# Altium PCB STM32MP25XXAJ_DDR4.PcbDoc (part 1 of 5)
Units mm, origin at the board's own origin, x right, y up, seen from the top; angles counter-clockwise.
Board outline 172 x 137 mm, 4 copper layers (Top Layer, Signal Layer 1, Signal Layer 2, Bottom Layer), stack 1.614 mm thick; 226 components, 313 nets, 1113 pads, 850 vias.
Unrouted connection lines stored in the file: 13.
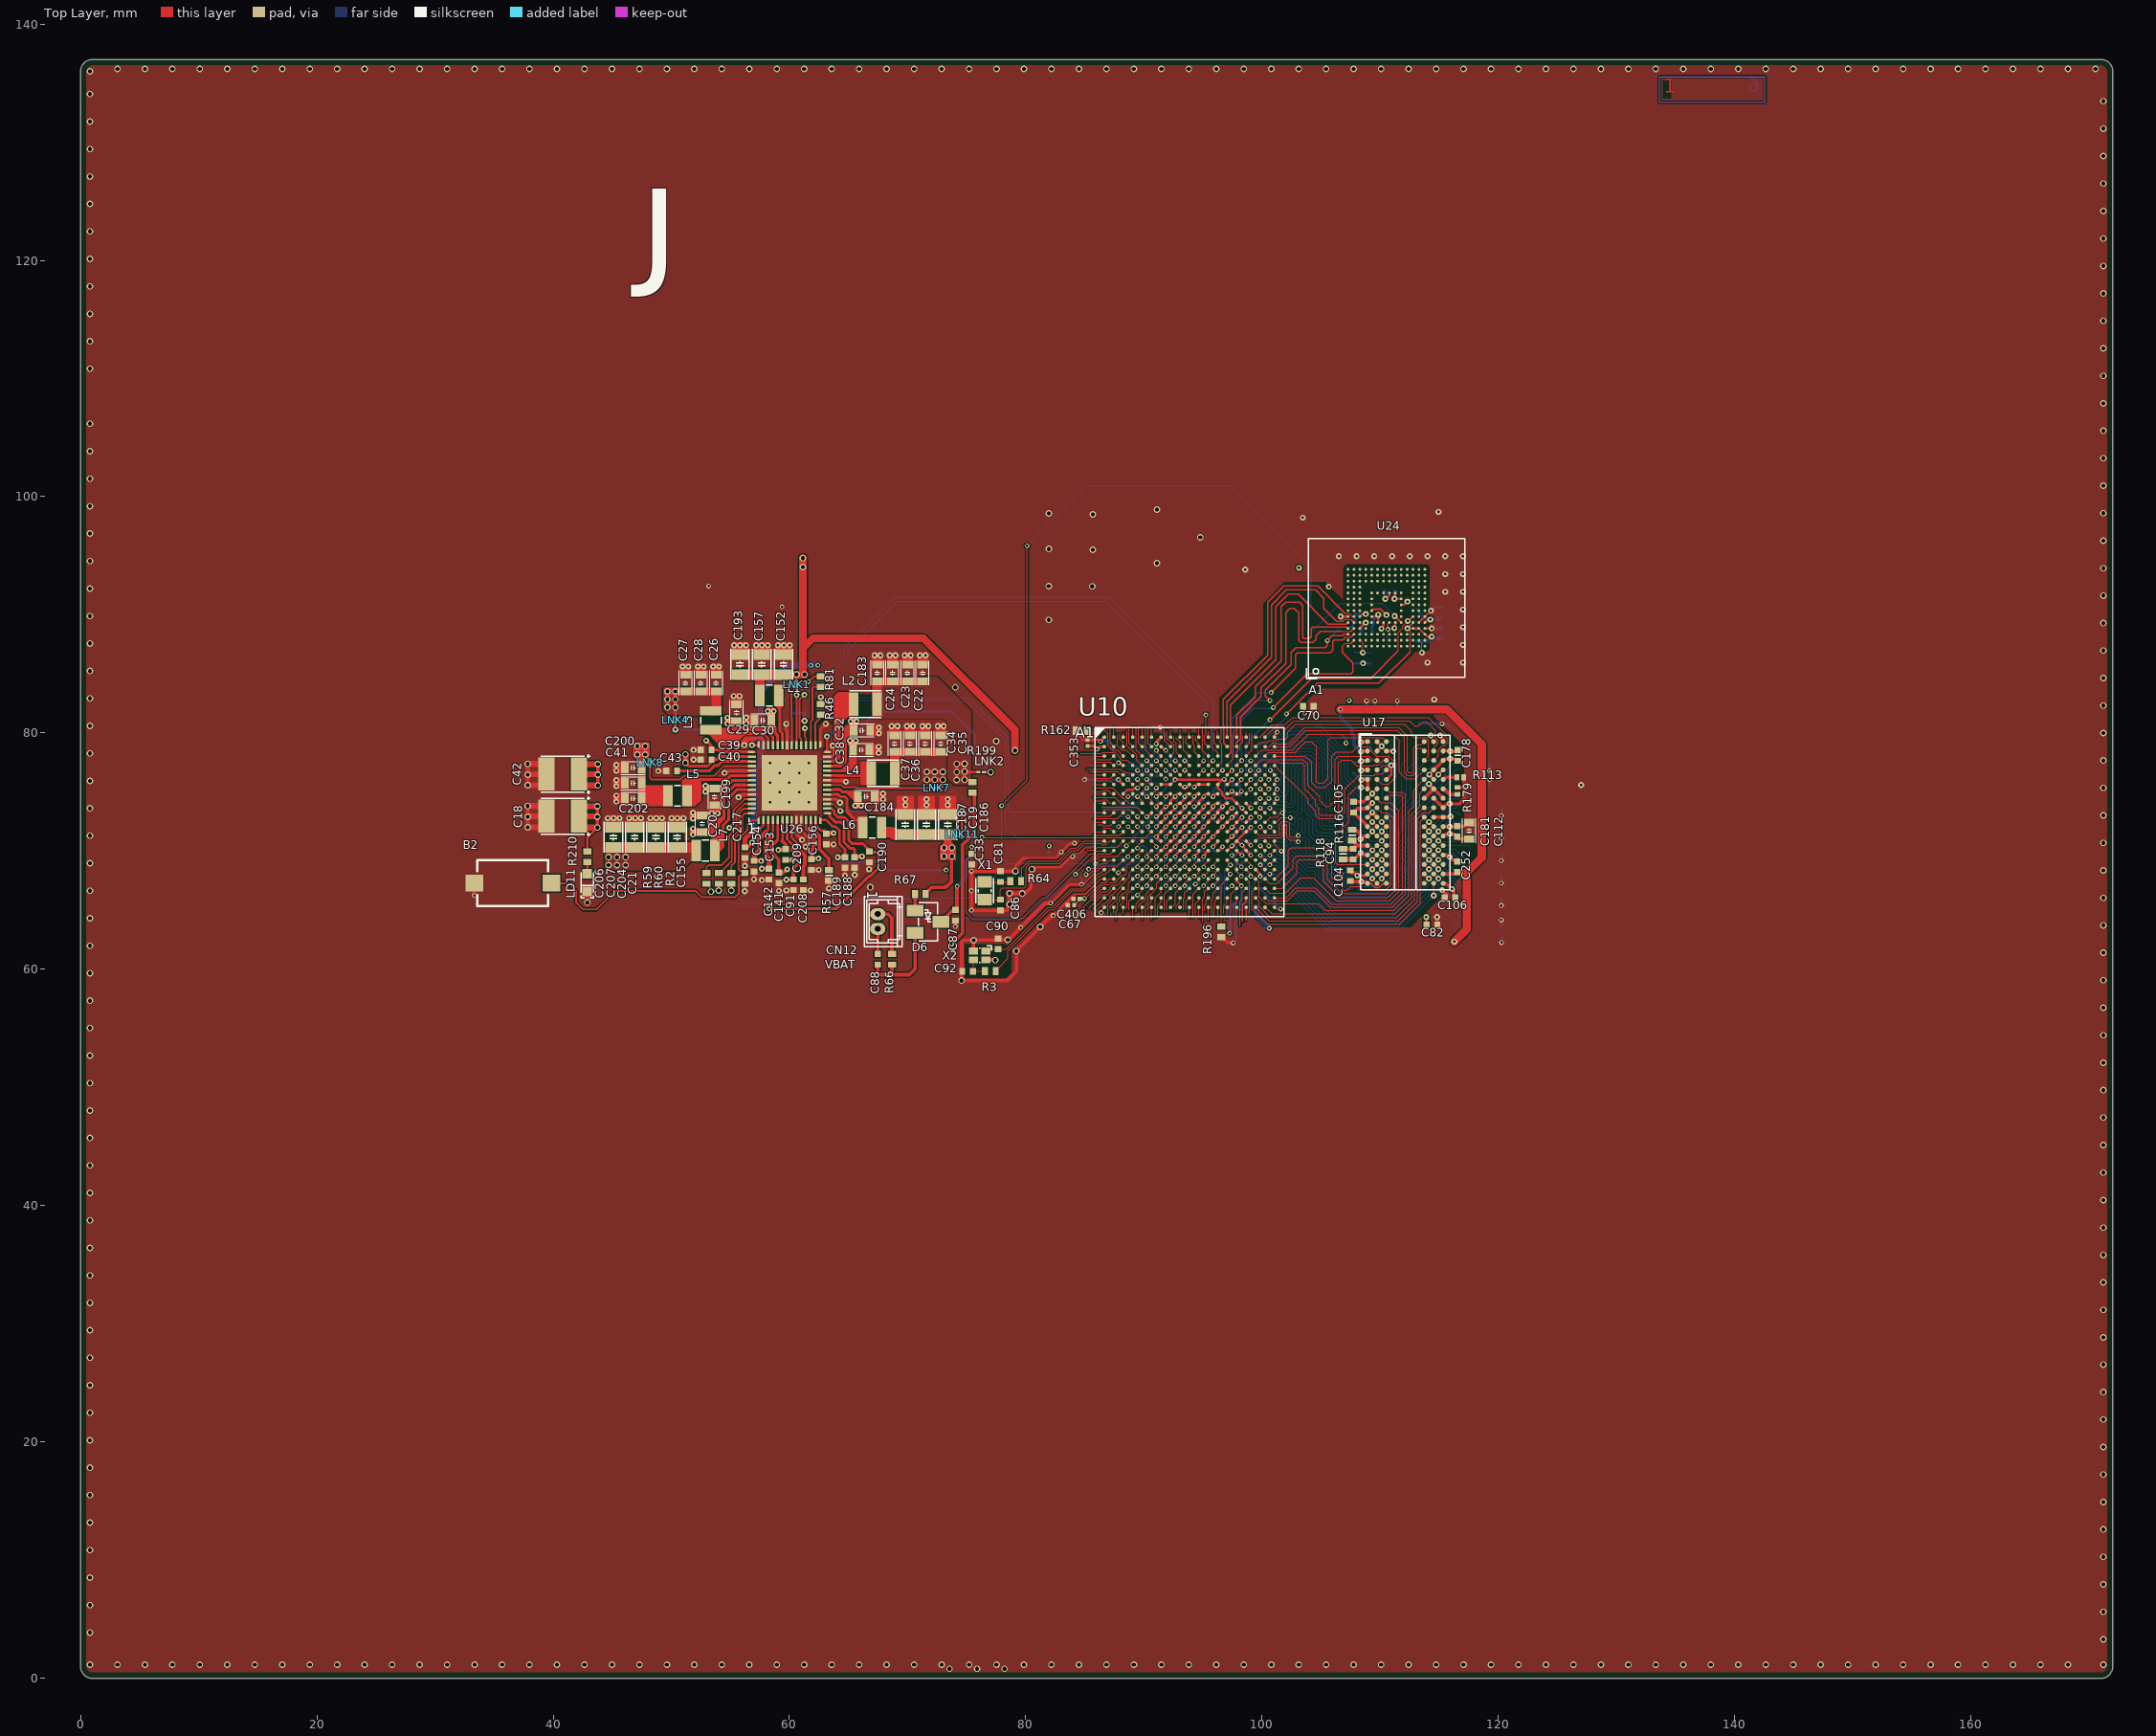
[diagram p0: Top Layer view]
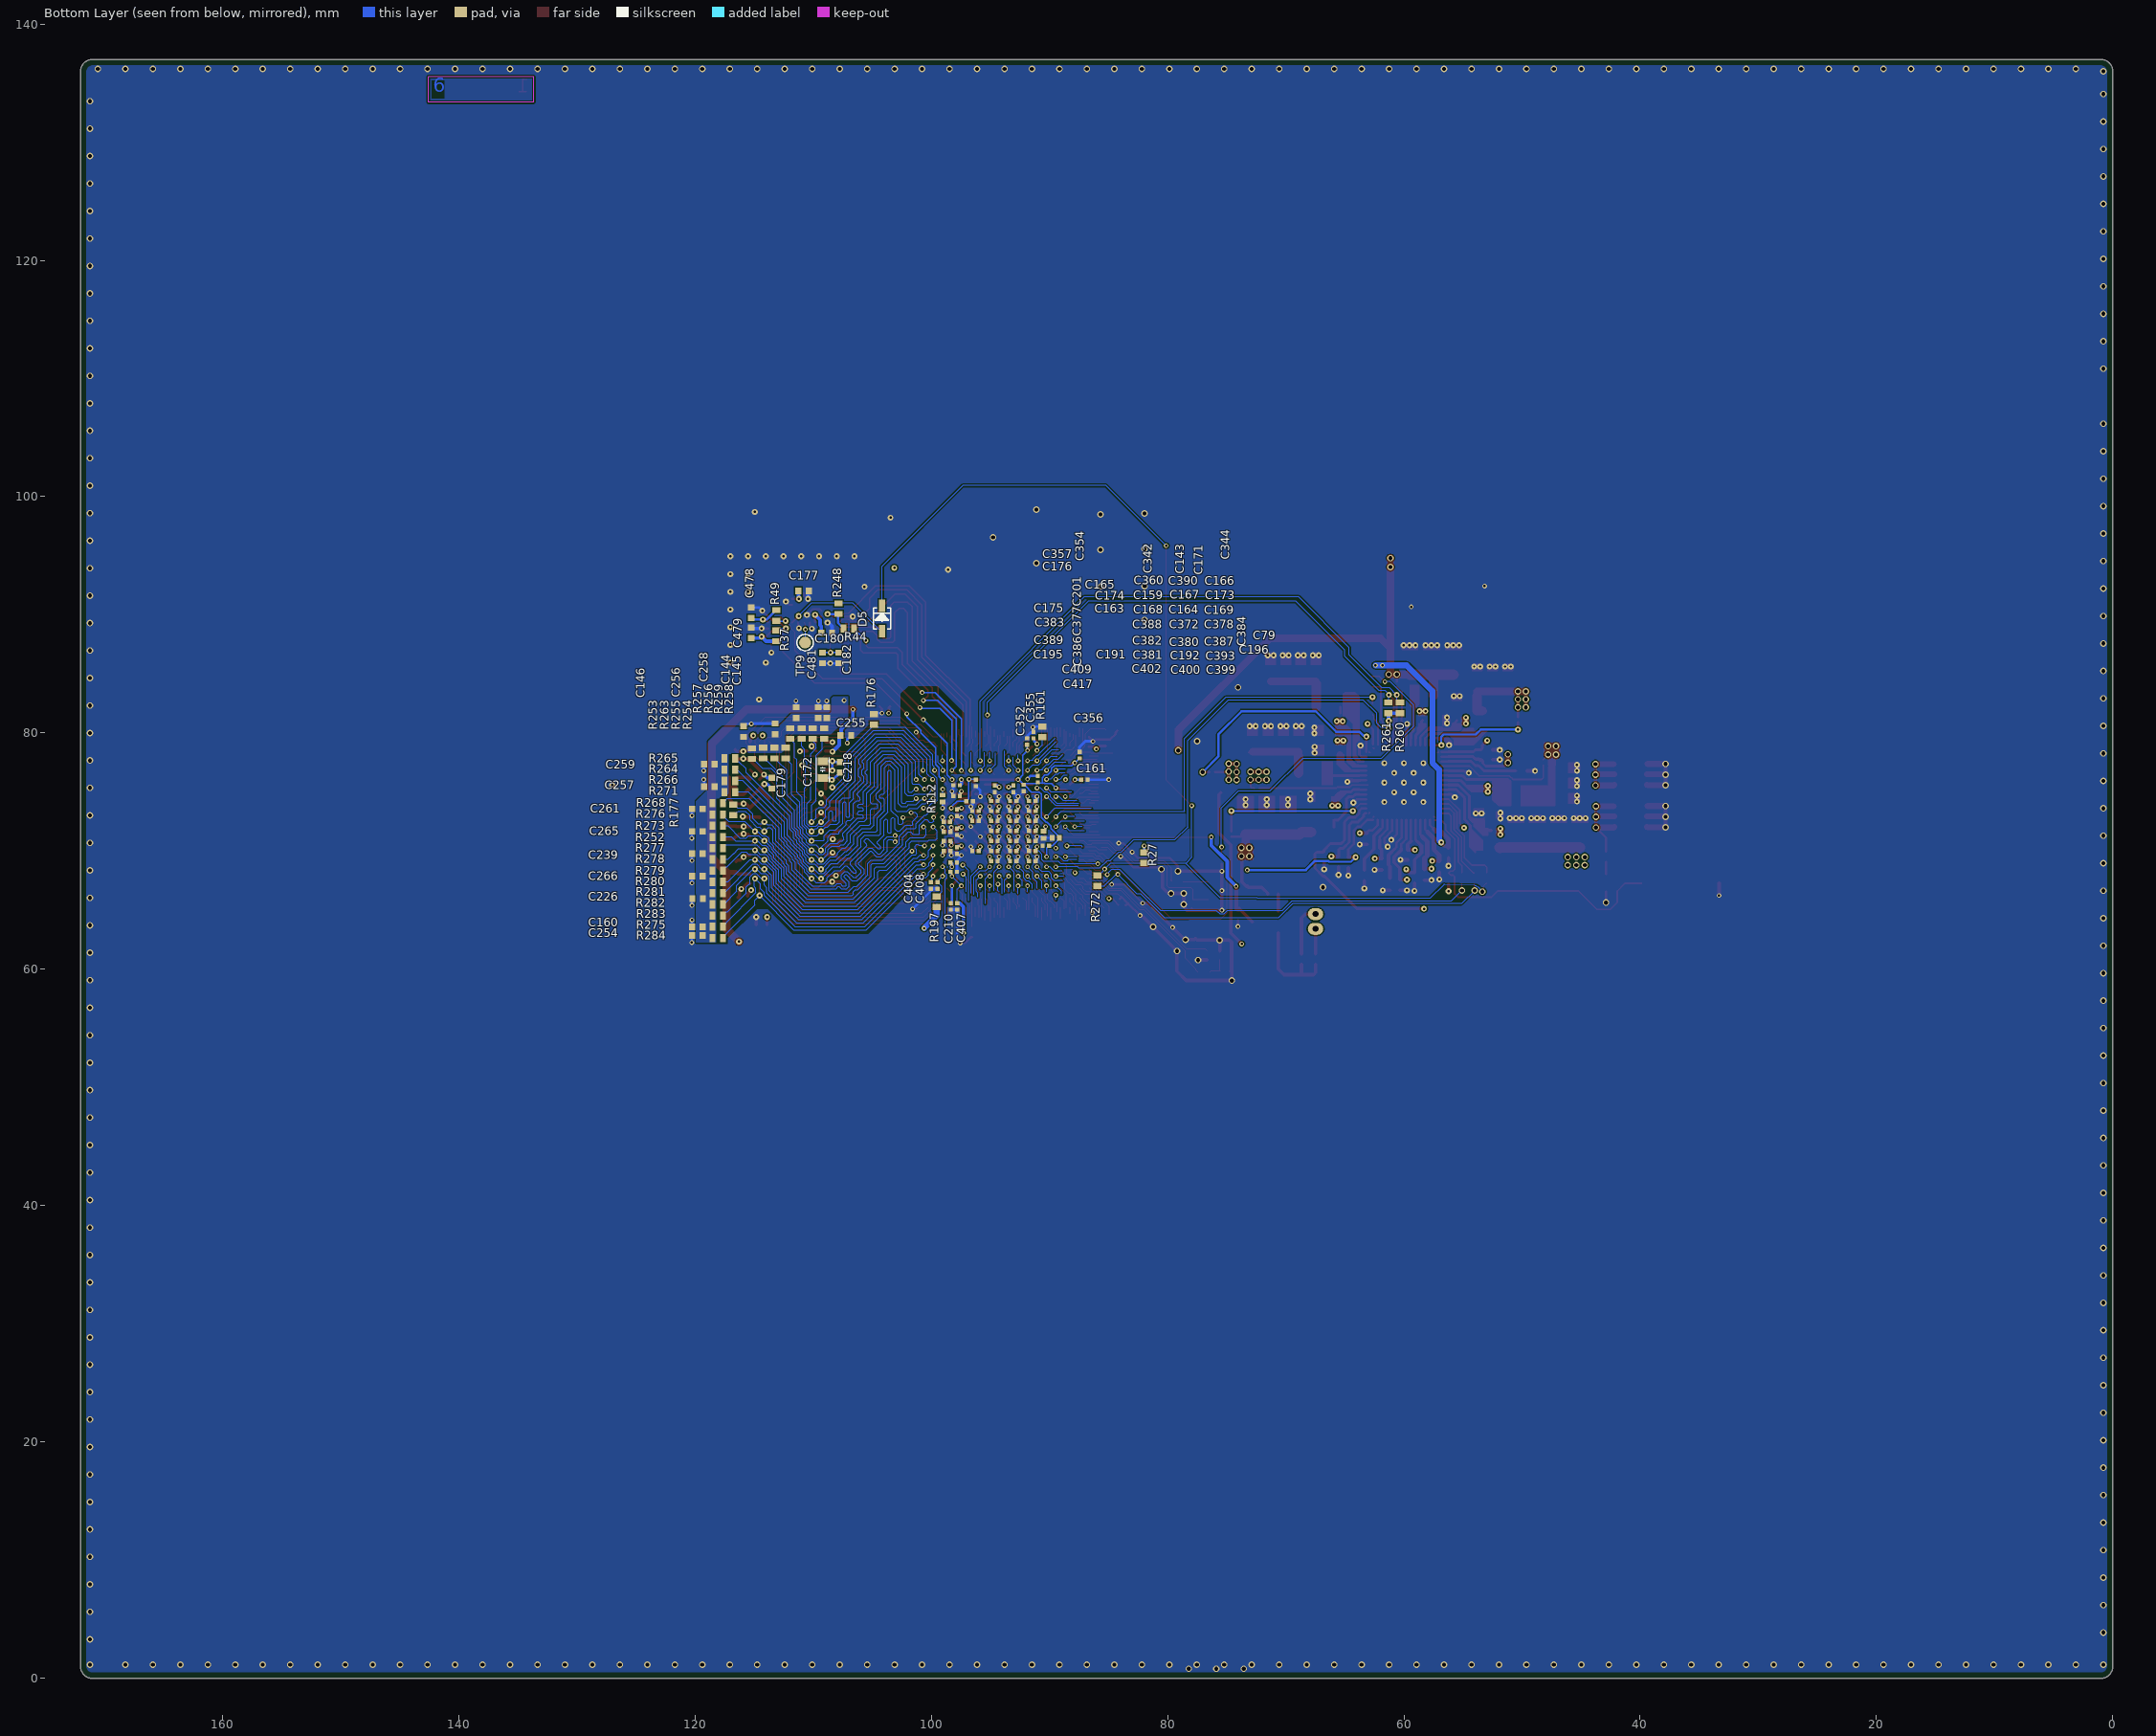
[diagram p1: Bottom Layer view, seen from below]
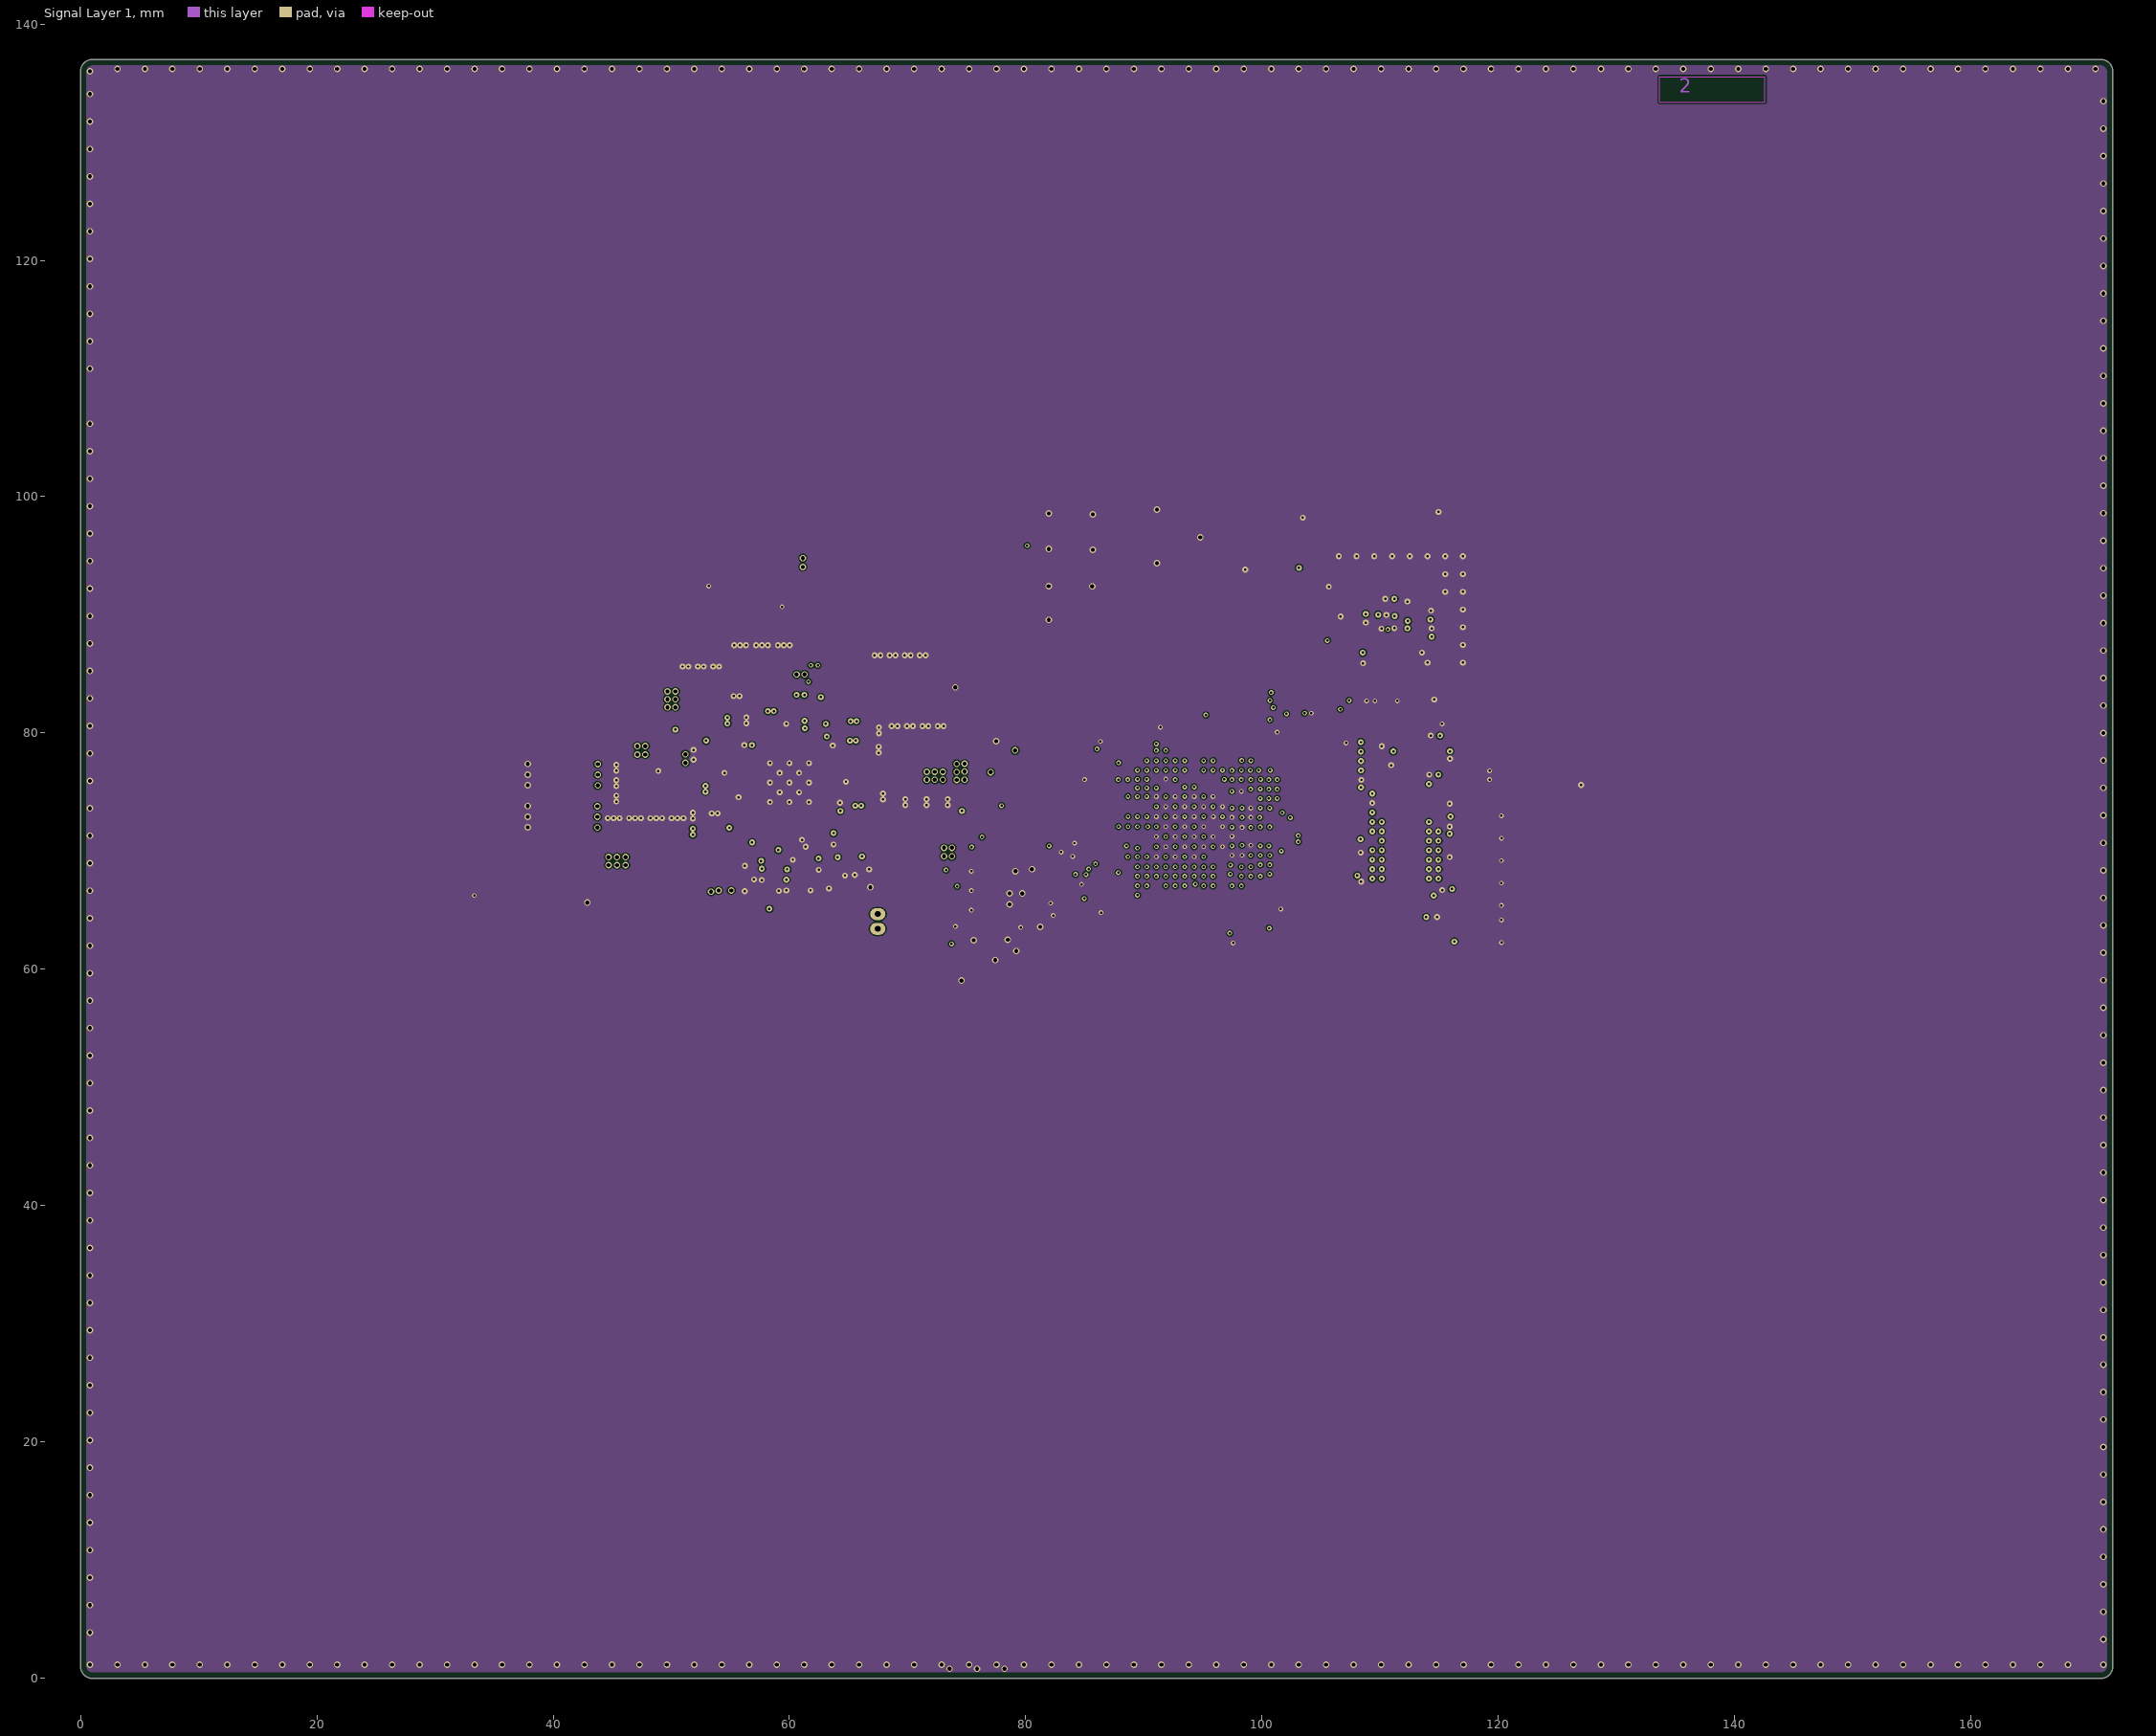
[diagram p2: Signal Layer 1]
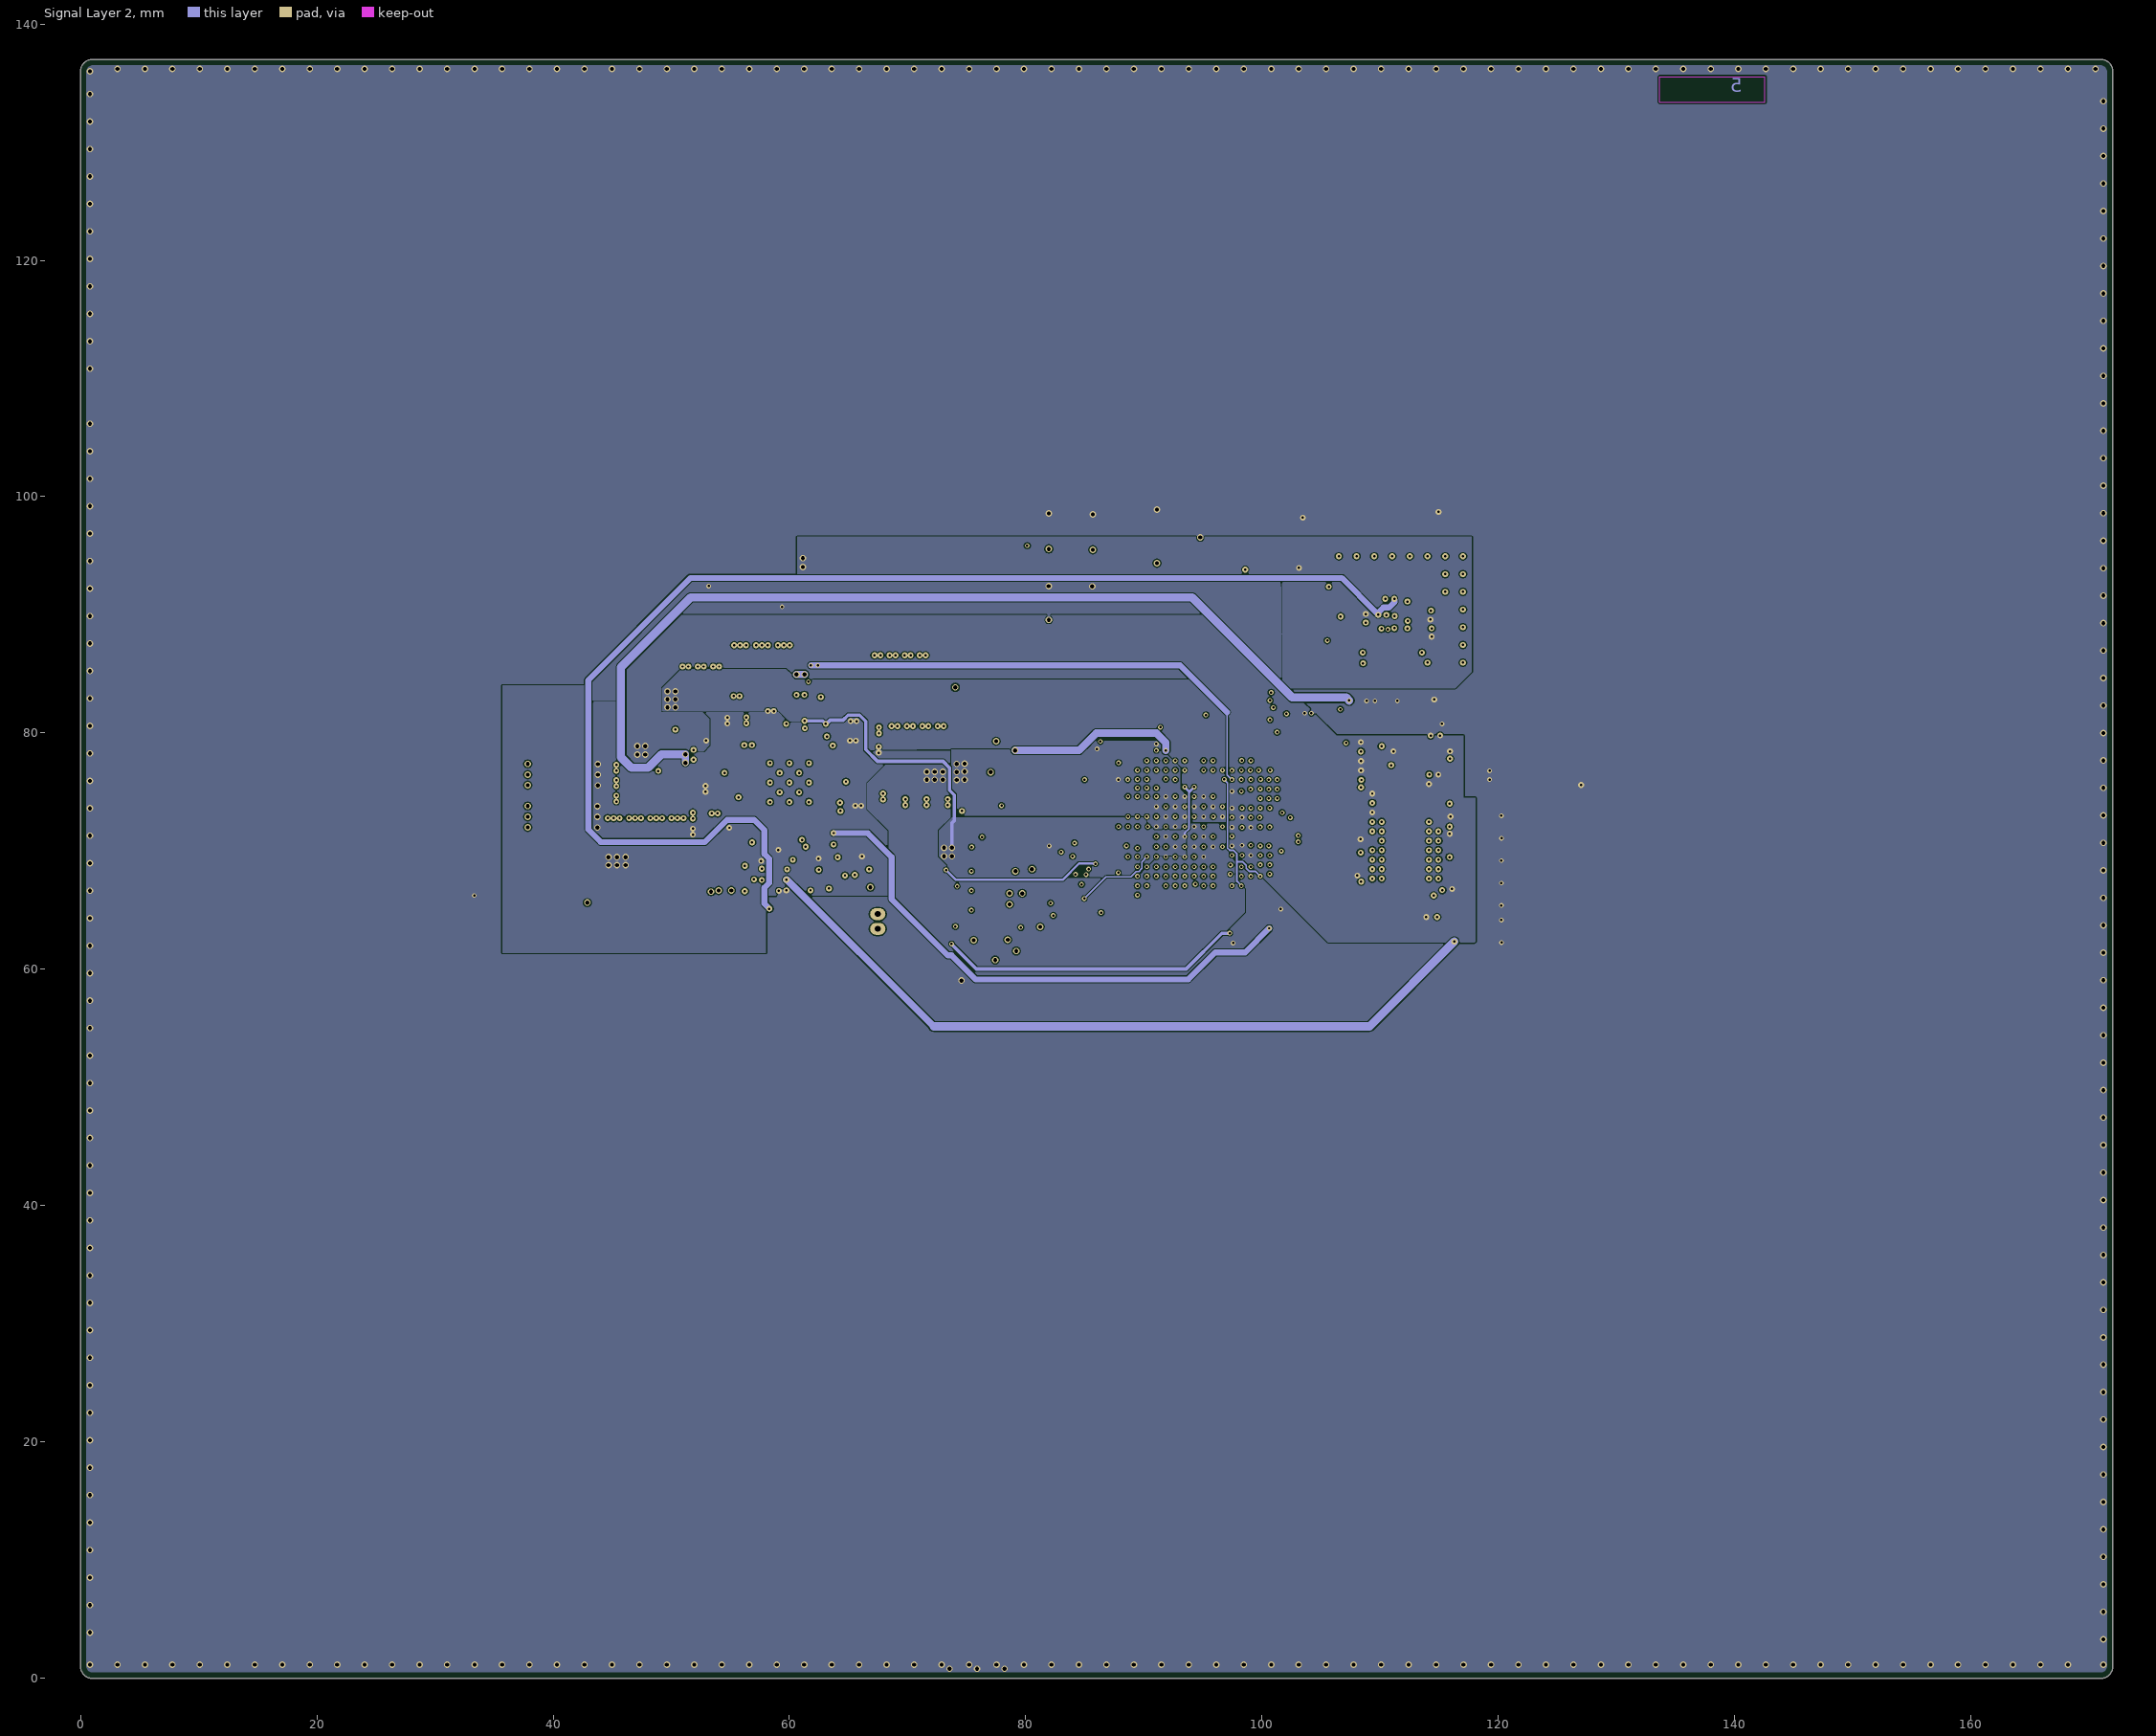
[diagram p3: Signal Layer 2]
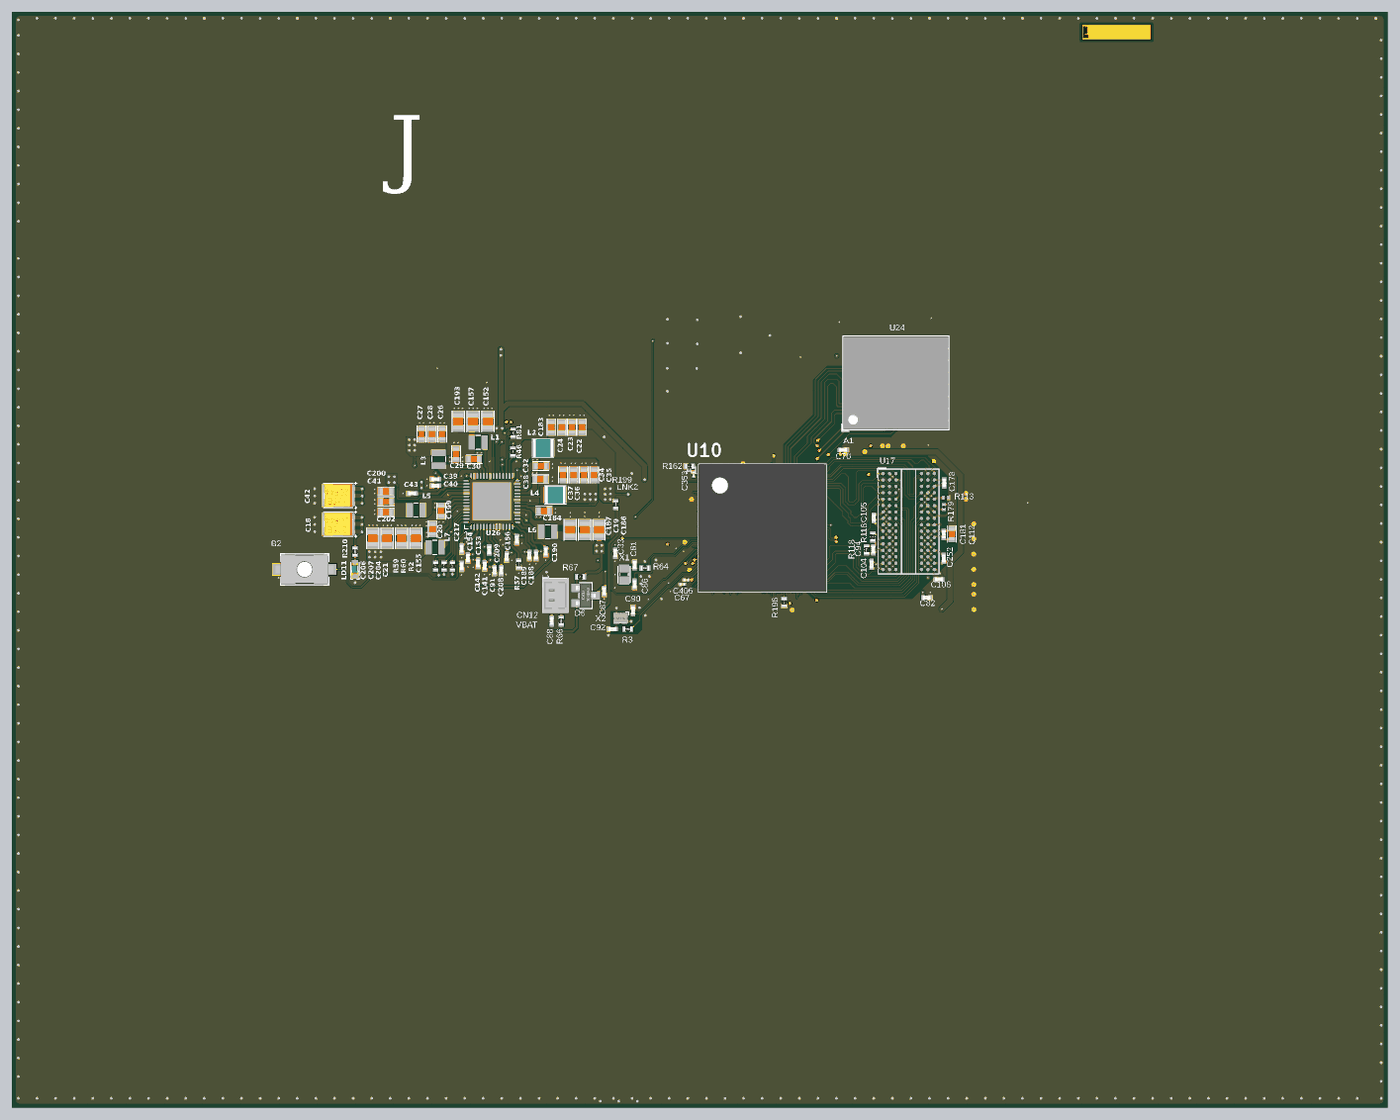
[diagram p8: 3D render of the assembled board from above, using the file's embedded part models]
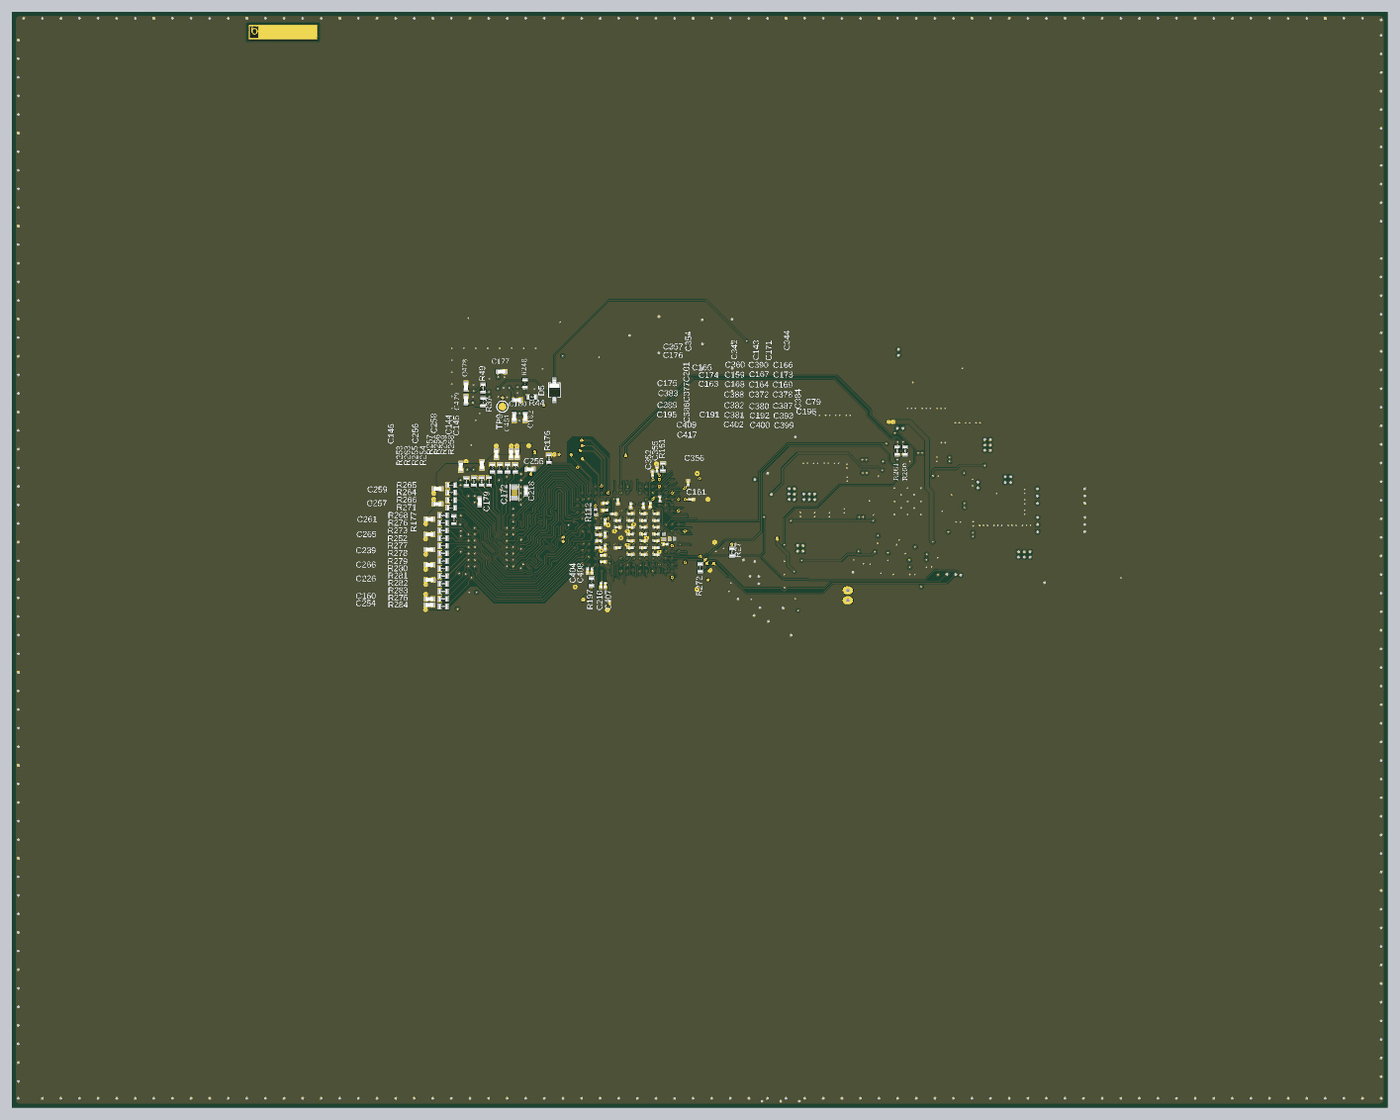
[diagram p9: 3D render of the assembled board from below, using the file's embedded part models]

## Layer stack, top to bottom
Top Solder: solder mask 0.025, Solder Resist, Dk 3.5
Top Layer: signal copper 0.037
Dielectric 1: prepreg 0.07, Dk 3.8
Signal Layer 1: signal copper 0.035
Dielectric 2: core 1.33, Dk 4.3
Signal Layer 2: signal copper 0.035
Dielectric 3: prepreg 0.07, Dk 3.8
Bottom Layer: signal copper 0.037
Bottom Solder: solder mask 0.025, Solder Resist, Dk 3.5

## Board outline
0,1 0,95 0,136 cw(c1,136) 1,137 171,137 cw(c171,136) 172,136 172,1 cw(c171,1) 171,0 1,0 cw(c1,1)

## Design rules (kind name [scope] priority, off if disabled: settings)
BoardOutlineClearance Silkscreen [OnLayer('Top Overlay') or OnLayer('Bottom Overlay')] p1: gap=0 ignorepadtopadclearanceinfootprint=FALSE
BoardOutlineClearance [All] p2: gap=0.5 ignorepadtopadclearanceinfootprint=FALSE
Clearance Clearance_Default [All] p1: gap=0.1 ignorepadtopadclearanceinfootprint=TRUE except(0: Arc-Hole Track-Hole SMDPad-Hole THPad-Hole Via-Hole Fill-Hole Poly-Hole Region-Hole Text-Hole; 0.09: Arc-Arc Arc-Track Arc-SMDPad Track-Track Track-SMDPad)
ComponentClearance [All] p1 off: gap=0.2 collisioncheckmode=3 verticalgap=0 showdistances=FALSE
DiffPairsRouting DiffPairsRouting_DDR_100R [InDifferentialPairClass('DPC_DDR_100R')] p1: maxlimit=0.16 minlimit=0.14 mostfreqgap=0.254 toplayer_mingap=0.16 toplayer_prefgap=0.16 toplayer_minwidth=0.09 toplayer_maxwidth=0.09 toplayer_prefwidth=0.09 bottomlayer_mingap=0.16 bottomlayer_prefgap=0.16 bottomlayer_minwidth=0.09 bottomlayer_maxwidth=0.09 bottomlayer_prefwidth=0.09 impedanceprofiledriven=TRUE impedanceprofileid={5106416E-43F8-41F8-8BCA-F68B3FB1C141} impedanceprofilevalue=100.000000 maxuncoupledlength=12.7
FanoutControl Fanout_BGA [IsBGA] p1: bgadir=Out bgaviamode=Closest fanoutstyle=Auto fanoutdirection=Alternating viagrid=0.025 // Fanout_BGA (Default Rule)
FanoutControl Fanout_LCC [IsLCC] p2: bgadir=Out bgaviamode=Closest fanoutstyle=Auto fanoutdirection=Alternating viagrid=0.025 // Fanout_LCC (Default Rule)
FanoutControl Fanout_SOIC [IsSOIC] p3: bgadir=Out bgaviamode=Closest fanoutstyle=Auto fanoutdirection=Alternating viagrid=0.025 // Fanout_SOIC (Default Rule)
FanoutControl Fanout_Small [(CompPinCount < 5)] p4: bgadir=Out bgaviamode=Closest fanoutstyle=Auto fanoutdirection=OutThenIn viagrid=0.025 // Fanout_Small (Default Rule)
FanoutControl Fanout_Default [All] p5: bgadir=Out bgaviamode=Closest fanoutstyle=Auto fanoutdirection=Alternating viagrid=0.025 // Fanout_Default (Default Rule)
HoleSize [All] p1: absolutevalues=TRUE maxlimit=10 minlimit=0.025 maxpercent=80.000 minpercent=20.000
HoleToHoleClearance [All] p1: gap=0.25 allowstackedmicrovias=TRUE
MinimumSolderMaskSliver [All] p1: minsoldermaskwidth=0.07
PlaneConnect [All] p1: planeconnectstyle=Direct reliefexpansion=0.508 reliefentries=4 reliefconductorwidth=0.21 reliefairgap=0.21
PolygonConnect PolygonConnect_Default [All] p1: connectstyle=Direct reliefconductorwidth=0.25 reliefentries=4 polygonreliefangle="90 Angle" airgapwidth=0.25
RoomDefinition U_PMIC [InComponentClass('U_PMIC')] p1: confinementstyle=ConfineIn formatcopy=TRUE lockcomponents=FALSE outline -226.399,-195.173 -175.599,-195.173 -175.599,-169.773 -226.399,-169.773
RoomDefinition U_eMMC [InComponentClass('U_eMMC')] p2: confinementstyle=ConfineIn formatcopy=TRUE lockcomponents=FALSE outline -226.399,-195.173 -175.599,-195.173 -175.599,-169.773 -226.399,-169.773
RoomDefinition U_DDR4_16bits [InComponentClass('U_DDR4_16bits')] p3: confinementstyle=ConfineIn formatcopy=TRUE lockcomponents=FALSE outline 173.143,1.397 598.552,1.397 598.552,17.691 173.143,17.691
RoutingVias RoutingVias_Default [All] p1: holewidth=0.15 width=0.4 viastyle="Through Hole" minholewidth=0.15 minwidth=0.4 maxholewidth=0.35 maxwidth=0.6 viatemplateguid#1={A479BBDC-94B7-4D18-B59D-B7A18B767B5F} viatemplateguid#2={564DD7E2-F718-4BCE-8A99-5417C9FECCB6} viatemplateguid#3={BA919398-BDEC-4FED-AED0-6BF9ED2A8C2F} viatemplateguid#4={BB8F4C89-420F-4EBC-9772-FD82009DE81A} viatemplateguid#5={3FF096CA-B7A5-4E0B-A50A-8B2CD18CCC19} viatemplatename#1=v55h35m40mx40 viatemplatename#2=v40h20m0mx0 viatemplatename#3=v50h25m30mx30 viatemplatename#4=v40h20m25mx25 viatemplatename#5=v50h25m0mx0
ShortCircuit ShortCircuit_Link200 [InPadClass('PC_LINK200')] p1: allowed=TRUE
SilkToSilkClearance [All] p1: silktosilkclearance=0.2
SilkToSolderMaskClearance [IsPad] p1: minsilkscreentomaskgap=0.015 clearancetoexposedcopper=TRUE
SolderMaskExpansion [All] p1: expansion=0.1 istentingtop=FALSE
ViasUnderSMD [InPadClass('PC_VIAS-IN-PAD_OK')] p1: allowed=TRUE
Width Width_Default [InNetClass('All Nets')] p1: maxlimit=10 minlimit=0.09 preferedwidth=0.1
16 further rules are at their usual default settings.

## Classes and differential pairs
net class eMMC.SDMMC2_D[0..7]: eMMC.SDMMC2_D0 eMMC.SDMMC2_D1 eMMC.SDMMC2_D2 eMMC.SDMMC2_D3 eMMC.SDMMC2_D4 eMMC.SDMMC2_D5 eMMC.SDMMC2_D6 eMMC.SDMMC2_D7
component class "U_STM32MP25XXAJ Power": C67 C79 C87 C88 C143 C159 C161 C163 C164 C165 C166 C167 C168 C169 C171 C173 C174 C175 C176 C191 C192 C195 C196 C201 C210 C342 C344 C352 C353 C354 C355 C356 C357 C360 C372 C377 C378 C380 C381 C382 C383 C384 C386 C387 C388 C389 C390 C393 C399 C400 C402 C404 C406 C407 C408 C409 C417 CN12 D6 R66 R67 R197 R199
component class "U_STM32MP25XXAJ I_Os": C33 C81 C86 C90 C92 R3 R27 R64 R161 R162 R196 R260 R261 R272 U10 X1 X2
component class U_PMIC: B2 C18 C19 C20 C21 C22 C23 C24 C26 C27 C28 C29 C30 C32 C34 C35 C36 C37 C38 C39 C40 C41 C42 C43 C91 C141 C142 C152 C153 C154 C155 C156 C157 C183 C184 C186 C187 C188 C189 C190 C193 C199 C200 C202 C204 C206 C207 C208 C209 C217 L1 L2 L3 L4 L5 L6 L7 LD11 LNK1 LNK2 LNK4 LNK7 LNK8 LNK11 R2 R46 R57 R59 R60 R81 R210 U26
component class U_eMMC: C177 C180 C182 C478 C479 C481 D5 R37 R44 R49 R248 TP9 U24
component class U_DDR4_16bits: C70 C82 C94 C104 C105 C106 C112 C144 C145 C146 C160 C172 C178 C179 C181 C218 C226 C239 C252 C254 C255 C256 C257 C258 C259 C261 C265 C266 R112 R113 R116 R118 R176 R177 R179 R252 R253 R254 R255 R256 R257 R258 R259 R263 R264 R265 R266 R268 R271 R273 R275 R276 R277 R278 R279 R280 R281 R282 R283 R284 U17
differential pair DDR_DQS1: +DDR_DQS1_P -DDR_DQS1_N
differential pair DDR_DQS0: +DDR_DQS0_P -DDR_DQS0_N
differential pair DDR_CLK: +DDR_CLK_P -DDR_CLK_N

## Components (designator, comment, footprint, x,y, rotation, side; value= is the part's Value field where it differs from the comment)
B2 "SW_PUSH_SMD_2P" SWI_WE_434121025816 36.59,67.295 r0 top value=434121025816
C18 "Cap_POL_TANA" CPOL_TCJ-B_1210_H210 40.812,72.961 r180 top value=100uF
C19 "Capacitor" C0805 71.6,72.25 r270 top value=22uF
C20 "Capacitor" C0603 52.6,72.325 r270 top value=10uF
C21 "Capacitor" C0805 50.5,71.173 r270 top value=22uF
C22 "Capacitor" C0603 71.275,85.075 r270 top value=22uF
C23 "Capacitor" C0603 70,85.075 r270 top value=22uF
C24 "Capacitor" C0603 68.725,85.075 r270 top value=22uF
C26 "Capacitor" C0603 53.8,84.225 r270 top value=22uF
C27 "Capacitor" C0603 51.2,84.225 r270 top value=22uF
C28 "Capacitor" C0603 52.5,84.225 r270 top value=22uF
C29 "Capacitor" C0603 55.525,81.725 r270 top value=10uF
C30 "Capacitor" C0603 57.75,81.075 r0 top value=10uF
C32 "Capacitor" C0603 66.125,80.225 r180 top value=10uF
C33 "Capacitor" C0402 75.425,69.325 r90 top value=10nF
C34 "Capacitor" C0603 71.5,79.1 r270 top value=22uF
C35 "Capacitor" C0603 72.8,79.1 r270 top value=22uF
C36 "Capacitor" C0603 70.2,79.1 r270 top value=22uF
C37 "Capacitor" C0603 68.9,79.1 r270 top value=22uF
C38 "Capacitor" C0603 66.075,78.575 r180 top value=10uF
C39 "Capacitor" C0402 52.945,78.575 r0 top value=10uF
C40 "Capacitor" C0402 52.945,77.75 r0 top value=10uF
C41 "Capacitor" C0603 46.775,75.75 r0 top value=22uF
C42 "Cap_POL_TANA" CPOL_TCJ-B_1210_H210 40.812,76.523 r180 top value=100uF
C43 "Capacitor" C0402 50.035,76.8 r0 top value=1uF
C67 "Capacitor" C0201_MURATA_GRM033_H0P3 83.825,65.425 r0 top value=1uF
C70 "Capacitor" C0402 103.925,82.25 r180 top value=100nF
C79 "Capacitor" C0201_H0P5 89.45,71.125 r180 bottom value=2.2uF
C81 "Capacitor" C0402 77.85,67.85 r90 top value=6.8pF
C82 "Capacitor" C0402 114.375,63.775 r180 top value=100nF
C86 "Capacitor" C0402 77.85,65.45 r270 top value=6.8pF
C87 "" C0402 74.05,64.575 r90 top value=100nF
C88 "Capacitor" C0402 67.475,60.85 r270 top value=2.2uF
C90 "Capacitor" C0402 77.65,62.15 r270 top value=6.8pF
C91 "Capacitor" C0402 60.345,67.16 r270 top value=4.7uF
C92 "Capacitor" C0402 75.075,59.825 r180 top value=6.8pF
C94 "Capacitor" C0402 107.7,69.75 r90 top value=100nF
C104 "Capacitor" C0402 107.475,67.925 r90 top value=100nF
C105 "Capacitor" C0402 107.75,73.725 r90 top value=100nF
C106 "Capacitor" C0402 115.9,66.05 r0 top value=100nF
C112 "Capacitor" C0603 117.525,71.725 r270 top value=10uF
C141 "Capacitor" C0402 59.1,67.75 r270 top value=4.7uF
C142 "Capacitor" C0402 58.275,68.06 r270 top value=4.7uF
C143 "Capacitor" C0201_MURATA_GRM033_H0P3 93.05,75.275 r90 bottom value=100nF
C144 "Capacitor" C0402 109.575,81.725 r270 bottom value=100nF
C145 "Capacitor" C0402 108.825,81.725 r270 bottom value=10uF
C146 "Capacitor" C0402 115.875,80.125 r270 bottom value=100nF
C152 "Capacitor" C0805 59.5,85.8 r270 top value=22uF
C153 "Capacitor" C0402 59.675,69.72 r90 top value=1uF
C154 "Capacitor" C0402 57,68.725 r90 top value=1uF
C155 "Capacitor" C0402 56.227,67.695 r90 top value=10nF
C156 "Capacitor" C0402 63.125,71.02 r90 top value=4.7uF
C157 "Capacitor" C0805 57.65,85.8 r270 top value=22uF
C159 "Capacitor" C0201_MURATA_GRM033_H0P3 94.65,73.4 r180 bottom value=1uF
C160 "Capacitor" C0402 119.8,63.6 r180 bottom value=100nF
C161 "Capacitor" C0201_MURATA_GRM033_H0P3 87.05,76.05 r0 bottom value=100nF
C163 "Capacitor" C0201_MURATA_GRM033_H0P3 96.25,72.55 r0 bottom value=1uF
C164 "Capacitor" C0201_MURATA_GRM033_H0P3 93.05,72.55 r180 bottom value=1uF
C165 "Capacitor" C0201_MURATA_GRM033_H0P3 96.75,74.225 r0 bottom value=100nF
C166 "Capacitor" C0201_MURATA_GRM033_H0P3 91.45,74.25 r0 bottom value=1uF
C167 "Capacitor" C0201_MURATA_GRM033_H0P3 93.05,73.4 r180 bottom value=1uF
C168 "Capacitor" C0201_MURATA_GRM033_H0P3 94.65,72.55 r0 bottom value=1uF
C169 "Capacitor" C0201_MURATA_GRM033_H0P3 91.45,72.55 r0 bottom value=1uF
C171 "Capacitor" C0201_MURATA_GRM033_H0P3 92.175,75.35 r90 bottom value=100nF
C172 "Capacitor" C0603 109.175,76.9 r90 bottom value=10uF
C173 "Capacitor" C0201_MURATA_GRM033_H0P3 91.45,73.4 r0 bottom value=1uF
C174 "Capacitor" C0201_MURATA_GRM033_H0P3 96.25,73.4 r0 bottom value=1uF
C175 "Capacitor" C0201_MURATA_GRM033_H0P3 98.675,72.475 r180 bottom value=1uF
C176 "Capacitor" C0201_MURATA_GRM033_H0P3 97.85,74.675 r180 bottom value=1uF
C177 "Capacitor" C0402 110.8,92.025 r0 bottom value=100nF
C178 "Capacitor" C0402 116.575,78.1 r90 top value=100nF
C179 "Capacitor" C0402 113.5,75.75 r270 bottom value=100nF
C180 "Capacitor" C0402 108.85,88.475 r0 bottom value=2.2uF
C181 "Capacitor" C0402 116.515,71.67 r270 top value=100nF
C182 "Capacitor" C0402 107.825,86.35 r90 bottom value=100nF
C183 "Capacitor" C0603 67.45,85.075 r270 top value=22uF
C184 "Capacitor" C0603 66.497,74.625 r180 top value=10uF
C186 "Capacitor" C0805 73.4,72.25 r270 top value=22uF
C187 "Capacitor" C0805 69.8,72.25 r270 top value=22uF
C188 "Capacitor" C0402 65.525,69.04 r90 top value=1uF
C189 "Capacitor" C0402 64.7,69.04 r90 top value=4.7uF
C190 "Capacitor" C0402 66.75,69.515 r270 top value=4.7uF
C191 "Capacitor" C0201_MURATA_GRM033_H0P3 96.25,70 r0 bottom value=1uF
C192 "Capacitor" C0201_MURATA_GRM033_H0P3 93.05,70 r180 bottom value=1uF
C193 "Capacitor" C0805 55.8,85.8 r270 top value=22uF
C195 "Capacitor" C0201_MURATA_GRM033_H0P3 98.65,70.025 r0 bottom value=1uF
C196 "Capacitor" C0201_MURATA_GRM033_H0P3 90.3,70.45 r180 bottom value=100nF
C199 "Capacitor" C0603 53.675,74.6 r90 top value=10uF
C200 "Capacitor" C0603 46.775,77.05 r0 top value=22uF
C201 "Capacitor" C0201_MURATA_GRM033_H0P3 97.825,73.25 r90 bottom value=1uF
C202 "Capacitor" C0603 46.775,74.45 r0 top value=22uF
C204 "Capacitor" C0805 48.7,71.173 r270 top value=22uF
C206 "Capacitor" C0805 45.1,71.173 r270 top value=22uF
C207 "Capacitor" C0805 46.9,71.173 r270 top value=22uF
C208 "Capacitor" C0402 61.17,67.16 r270 top value=4.7uF
C209 "Capacitor" C0402 61.85,68.87 r90 top value=4.7uF
C210 "Capacitor" C0201_MURATA_GRM033_H0P3 98.35,65.325 r90 bottom value=100nF
C217 "Capacitor" C0402 56.225,69.87 r270 top value=4.7uF
C218 "Capacitor" C0402 107.725,77.1 r90 bottom value=100nF
C226 "Capacitor" C0402 119.775,65.975 r180 bottom value=100nF
C239 "Capacitor" C0402 119.8,69.775 r180 bottom value=100nF
C252 "Capacitor" C0402 116.515,68.67 r270 top value=100nF
C254 "Capacitor" C0402 119.8,62.85 r180 bottom value=10uF
C255 "Capacitor" C0402 107.225,79.8 r0 bottom value=100nF
C256 "Capacitor" C0402 113.225,80.35 r270 bottom value=100nF
C257 "Capacitor" C0402 118.775,75.475 r180 bottom value=100nF
C258 "Capacitor" C0402 111.425,81.725 r270 bottom value=100nF
C259 "Capacitor" C0402 118.775,77.375 r180 bottom value=100nF
C261 "Capacitor" C0402 119.8,73.575 r180 bottom value=100nF
C265 "Capacitor" C0402 119.8,71.675 r180 bottom value=100nF
C266 "Capacitor" C0402 119.8,67.875 r180 bottom value=100nF
C342 "Capacitor" C0201_MURATA_GRM033_H0P3 94.625,75.275 r90 bottom value=100nF
C344 "Capacitor" C0201_MURATA_GRM033_H0P3 90.975,76.1 r270 bottom value=100nF
C352 "Capacitor" C0201_MURATA_GRM033_H0P3 91.9,79.275 r270 bottom value=100nF
C353 "Capacitor" C0201_MURATA_GRM033_H0P3 85.225,79.175 r270 top value=100nF
C354 "Capacitor" C0201_MURATA_GRM033_H0P3 96.224,75.776 r90 bottom value=100nF
C355 "Capacitor" C0201_MURATA_GRM033_H0P3 91.35,79.825 r270 bottom value=100nF
C356 "Capacitor" C0201_MURATA_GRM033_H0P3 87.45,78.125 r270 bottom value=100nF
C357 "Capacitor" C0201_MURATA_GRM033_H0P3 97.85,75.575 r180 bottom value=100nF
C360 "Capacitor" C0201_MURATA_GRM033_H0P3 94.65,74.25 r180 bottom value=1uF
C372 "Capacitor" C0201_MURATA_GRM033_H0P3 93.05,71.7 r180 bottom value=1uF
C377 "Capacitor" C0201_MURATA_GRM033_H0P3 97.825,71.65 r90 bottom value=1uF
C378 "Capacitor" C0201_MURATA_GRM033_H0P3 91.45,71.7 r180 bottom value=1uF
C380 "Capacitor" C0201_MURATA_GRM033_H0P3 93.05,70.85 r0 bottom value=1uF
C381 "Capacitor" C0201_MURATA_GRM033_H0P3 94.65,70 r180 bottom value=1uF
C382 "Capacitor" C0201_MURATA_GRM033_H0P3 94.65,70.85 r0 bottom value=1uF
C383 "Capacitor" C0201_MURATA_GRM033_H0P3 98.65,71.625 r0 bottom value=1uF
C384 "Capacitor" C0201_H0P5 90.5,71.375 r90 bottom value=4.7uF
C386 "Capacitor" C0201_MURATA_GRM033_H0P3 97.825,70.05 r90 bottom value=1uF
C387 "Capacitor" C0201_MURATA_GRM033_H0P3 91.45,70.85 r180 bottom value=1uF
C388 "Capacitor" C0201_MURATA_GRM033_H0P3 94.65,71.7 r180 bottom value=1uF
C389 "Capacitor" C0201_MURATA_GRM033_H0P3 98.65,70.875 r0 bottom value=1uF
C390 "Capacitor" C0201_MURATA_GRM033_H0P3 93.05,74.25 r0 bottom value=1uF
C393 "Capacitor" C0201_MURATA_GRM033_H0P3 91.45,70 r180 bottom value=100nF
C399 "Capacitor" C0201_MURATA_GRM033_H0P3 91.45,69.15 r180 bottom value=1uF
C400 "Capacitor" C0201_MURATA_GRM033_H0P3 93.05,69.15 r0 bottom value=1uF
C402 "Capacitor" C0201_MURATA_GRM033_H0P3 94.65,69.15 r0 bottom value=1uF
C404 "Capacitor" C0201_MURATA_GRM033_H0P3 100.025,67.1 r90 bottom value=100nF
C406 "Capacitor" C0201_MURATA_GRM033_H0P3 84.3,65.975 r0 top value=100nF
C407 "Capacitor" C0201_MURATA_GRM033_H0P3 97.8,65.325 r90 bottom value=100nF
C408 "Capacitor" C0201_MURATA_GRM033_H0P3 99.475,67.101 r90 bottom value=100nF
C409 "Capacitor" C0201_MURATA_GRM033_H0P3 98.1,69.05 r0 bottom value=100nF
C417 "Capacitor" C0201_MURATA_GRM033_H0P3 98.1,68.25 r0 bottom value=100nF
C478 "Capacitor" C0402 115.225,90.175 r270 bottom value=2.2uF
C479 "Capacitor" C0402 115.225,88.475 r270 bottom value=100nF
C481 "Capacitor" C0402 109.2,86.35 r90 bottom value=2.2uF
CN12 "" CON_MOLEX_53047-0210 67.475,64.05 r270 top value="Header 2x1"
D5 "BAT60JFILM" DIO_SOD323 104.175,89.7 r90 bottom
D6 "DIODE_3P_DUAL_COMMON_CATHODE" DIO_SOT23 71.725,64.025 r270 top value=BAT54CFILM
L1 "Inductor" IND_2016_MURATA_LQM2MPN2R2NG0 58.295,83.175 r180 top value=2.2uH
L2 "Inductor" IND_2520_TOKO_DFE252012P 66.415,82.45 r0 top value=0.68µH
L3 "Inductor" IND_2016_MURATA_LQM2MPN2R2NG0 53.35,81.075 r90 top value=0.68uH
L4 "Inductor" IND_2520_TOKO_DFE252012P 67.925,76.6 r0 top value=0.68µH
L5 "Inductor" IND_2016_MURATA_LQM2MPN2R2NG0 50.525,74.7 r180 top value=0.68uH
L6 "Inductor" IND_2016_MURATA_LQM2MPN2R2NG0 67,72 r0 top value=2.2uH
L7 "Inductor" IND_2016_MURATA_LQM2MPN2R2NG0 52.9,70.05 r180 top value=0.68uH
LD11 "LED_green" LED_0603_OSRAM_LG-Q396-PS-35_GREEN_1A2K_H0P4 42.887,67.327 r270 top value=GREEN
LNK1 "link_200" LINK200 60.6,84.123 r0 top
LNK2 "link_200" LINK200 76.219,76.687 r90 top
LNK4 "link_200" LINK200 50.35,81.125 r180 top
LNK7 "link_200" LINK200 72.45,75.35 r270 top
LNK8 "link_200" LINK200 48.2,77.498 r0 top
LNK11 "link_200" LINK200 74.6,71.44 r180 top
R2 "" R0402 55.08,67.695 r90 top value=0R
R3 "" R0402 77,59.85 r0 top value=0R
R27 "Resistor" R0402 81.975,69.45 r90 bottom value=10K
R37 "Resistor" R0402 113.1,88.225 r270 bottom value=10K
R44 "Resistor" R0402 106.975,88.85 r0 bottom value=10K
R46 "" R0402 62.65,81.998 r270 top value=0R
R49 "Resistor" R0402 113.1,89.95 r90 bottom value=10K
R57 "" R0402 63.35,67.95 r90 top value=0R
R59 "" R0402 52.98,67.695 r90 top value=0R
R60 "" R0402 54.03,67.695 r90 top value=0R
R64 "" R0402 79.15,67.45 r180 top value=0R
R66 "Resistor" R0402 68.675,60.845 r270 top value=20R
R67 "Resistor" R0402 71.075,66.375 r0 top value=0R
R81 "" R0402 62.663,84.348 r270 top value=0R
R112 "Resistor" R0201_H0P23 99.028,74.45 r90 bottom value=240R
R113 "Resistor" R0201_H0P23 116.775,76.25 r180 top value=240R
R116 "Resistor" R0402 107.625,71.36 r270 top value=1K
R118 "Resistor" R0402 106.855,69.75 r90 top value=1K
R161 "Resistor" R0402 90.6,80.1 r90 bottom value=200R
R162 "Resistor" R0402 84.7,80.2 r180 top value=200R
R176 "Resistor" R0402 104.85,81.15 r270 bottom value=10K
R177 "Resistor" R0402 116.75,73.5 r90 bottom value=100R
R179 "Resistor" R0201_H0P23 116.525,75.1 r270 top value=240R
R196 "Resistor" R0402 96.55,63.175 r90 top value=200R
R197 "" R0402 99.55,65.725 r90 bottom value=0R
R199 "" R0402 75.5,75.4 r270 top value=0R
R210 "Resistor" R0402 42.887,69.52 r270 top value=270R
R248 "Resistor" R0402 107.85,90.525 r270 bottom value=10K
R252 "Resistor" R0402 118.075,71.2 r0 bottom value=56R
R253 "Resistor" R0402 115.175,78.25 r90 bottom value=56R
R254 "Resistor" R0402 112.325,78.3 r90 bottom value=56R
R255 "Resistor" R0402 113.275,78.3 r90 bottom value=56R
R256 "Resistor" R0402 110.975,79.95 r90 bottom value=56R
R257 "Resistor" R0402 111.925,79.95 r90 bottom value=56R
R258 "Resistor" R0402 109.075,79.95 r90 bottom value=56R
R259 "Resistor" R0402 110.025,79.95 r90 bottom value=56R
R260 "Resistor" R0402 60.33,82.13 r270 bottom value=1K5
R261 "Resistor" R0402 61.305,82.13 r270 bottom value=1K5
R263 "Resistor" R0402 114.225,78.3 r90 bottom value=56R
R264 "Resistor" R0402 117.05,76.9 r0 bottom value=56R
R265 "Resistor" R0402 117.05,77.85 r0 bottom value=56R
R266 "Resistor" R0402 117.05,75.95 r0 bottom value=56R
R268 "Resistor" R0402 118.075,74.05 r0 bottom value=56R
R271 "Resistor" R0402 117.05,75 r0 bottom value=56R
R272 "Resistor" R0402 85.925,67.5 r270 bottom value=10K
R273 "Resistor" R0402 118.075,72.15 r0 bottom value=56R
R275 "Resistor" R0402 118.075,63.6 r0 bottom value=56R
R276 "Resistor" R0402 118.075,73.1 r0 bottom value=56R
R277 "Resistor" R0402 118.075,70.25 r0 bottom value=56R
R278 "Resistor" R0402 118.075,69.3 r0 bottom value=56R
R279 "Resistor" R0402 118.075,68.35 r0 bottom value=56R
R280 "Resistor" R0402 118.075,67.4 r0 bottom value=56R
R281 "Resistor" R0402 118.075,66.45 r0 bottom value=56R
R282 "Resistor" R0402 118.075,65.5 r0 bottom value=56R
R283 "Resistor" R0402 118.075,64.55 r0 bottom value=56R
R284 "Resistor" R0402 118.075,62.65 r0 bottom value=56R
TP9 "Test Point" TP_SMD_1MM 110.675,87.65 r90 bottom value=N/A
U10 "IC_STM32MP257FAJ3" ICC_TFBGA361_16X16_P080 93.85,72.45 r0 top locked value=STM32MP257FAJ3
U17 "MT40A2G16TBB-062E:F" ICC_FBGA96_TBB_7P5X13_P080 112.125,73.275 r0 top
U24 "eMMC_THGBMTG5D1LBAIL" ICC_P-WFBGA153_13X11P5_P050 110.525,90.6 r0 top locked value=THGBMTG5D1LBAIL
U26 "STPMIC25APQR" ICC_QFN56-EPAD_6P5X6P5_P040 60,75.8 r90 top
X1 "XTAL_2_PINS" CRY_NX2012SA_2P 76.525,66.65 r270 top value=32.768KHz
X2 "XTAL_4_PINS" CRY_NX1612SA_4P 76.098,61.176 r180 top value=40MHz

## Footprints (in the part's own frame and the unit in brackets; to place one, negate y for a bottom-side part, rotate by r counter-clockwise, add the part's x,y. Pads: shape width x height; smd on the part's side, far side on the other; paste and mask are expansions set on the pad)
C0201_H0P5 [mm] "MCD-01534"
  rect 0.4x0.5 smd mask+0.05: 1(-0.3,0) 2(0.3,0)
  body extent -0.35,-0.2 0.35,0.2, height 0.55
C0201_MURATA_GRM033_H0P3 [mm]
  rect 0.35x0.35 smd mask+0.05: 1(-0.275,0) 2(0.275,0)
  body extent -0.32,-0.17 0.32,0.17, height 0.33
C0402 [mm]
  rect 0.51x0.56 smd mask+0.05: 1(-0.45,0) 2(0.45,0)
  body extent -0.5,-0.3 0.5,0.3, height 0.4
C0603 [mm]
  rect 0.64x0.89 smd mask+0.05: 1(-0.7,0) 2(0.7,0)
  silkscreen extent -1.05,-0.55 1.02,0.55, body extent -0.9,-0.5 0.9,0.5, height 1.4
C0805 [mm]
  rect 0.9x1.4 smd mask+0.05: 1(-0.85,0) 2(0.85,0)
  silkscreen extent -1.3,-0.77 1.3,0.77, body extent -1.1,-0.7 1.1,0.7, height 1.35
CON_MOLEX_53047-0210 [mm]
  oval 1x1.3 hole 0.5 mask+0.05: 1(-0.625,0) 2(0.625,0)
  silkscreen extent -2.12,-1.15 2.13,2.05, body extent -2.13,-1.15 2.13,2.05, height 4.2
CPOL_TCJ-B_1210_H210 [mm] "MCD-01791"
  rect 1.35x2.8 smd mask+0.05: 1(-1.375,0) 2(1.375,0)
  silkscreen extent -2.33,-1.68 1.85,1.68, body extent -1.85,-1.5 1.85,1.5, height 2.11
CRY_NX1612SA_4P [mm] "MCD-02262"
  rect 0.75x0.6 smd mask+0.038: 1(-0.525,-0.375) 2(0.525,-0.375) 3(0.525,0.375) 4(-0.525,0.375)
  silkscreen extent -1.02,-0.8 0.03,0.6, body extent -0.8,-0.6 0.8,0.6, height 0.51
CRY_NX2012SA_2P [mm]
  rect 1x1.25 smd mask+0.05: 1(-0.75,0) 2(0.75,0)
  silkscreen extent -1.05,-0.75 1.05,0.75, body extent -1.05,-0.63 1.05,0.63, height 0.6
DIO_SOD323 [mm]
  rect 1.06x0.54 smd mask+0.05: 1(-1.07,0) 2(1.07,0)
  silkscreen extent -0.9,-0.72 0.9,0.72, body extent -1.3,-0.78 1.3,0.78, height 1.17
DIO_SOT23 [mm]
  rect 1x1.4 smd mask+0.05: 1(-0.95,-1.1) 2(0.95,-1.1) 3(0,1.1)
  silkscreen extent -1.63,-0.82 1.63,0.82, body extent -1.56,-1.25 1.56,1.25, height 1.1
ICC_FBGA96_TBB_7P5X13_P080 [mm] "MCD-04020"
  round 0.42 smd mask+0.05: A1(-3.2,6) A2(-2.4,6) A3(-1.6,6) A7(1.6,6) A8(2.4,6) A9(3.2,6) B1(-3.2,5.2) B2(-2.4,5.2) B3(-1.6,5.2) B7(1.6,5.2) B8(2.4,5.2) B9(3.2,5.2) C1(-3.2,4.4) C2(-2.4,4.4) C3(-1.6,4.4) C7(1.6,4.4) C8(2.4,4.4) C9(3.2,4.4) D1(-3.2,3.6) D2(-2.4,3.6) D3(-1.6,3.6) D7(1.6,3.6) D8(2.4,3.6) D9(3.2,3.6) E1(-3.2,2.8) E2(-2.4,2.8) E3(-1.6,2.8) E7(1.6,2.8) E8(2.4,2.8) E9(3.2,2.8) F1(-3.2,2) F2(-2.4,2) F3(-1.6,2) F7(1.6,2) F8(2.4,2) F9(3.2,2) G1(-3.2,1.2) G2(-2.4,1.2) G3(-1.6,1.2) G7(1.6,1.2) G8(2.4,1.2) G9(3.2,1.2) H1(-3.2,0.4) H2(-2.4,0.4) H3(-1.6,0.4) H7(1.6,0.4) H8(2.4,0.4) H9(3.2,0.4) J1(-3.2,-0.4) J2(-2.4,-0.4) J3(-1.6,-0.4) J7(1.6,-0.4) J8(2.4,-0.4) J9(3.2,-0.4) K1(-3.2,-1.2) K2(-2.4,-1.2) K3(-1.6,-1.2) K7(1.6,-1.2) K8(2.4,-1.2) K9(3.2,-1.2) L1(-3.2,-2) L2(-2.4,-2) L3(-1.6,-2) L7(1.6,-2) L8(2.4,-2) L9(3.2,-2) M1(-3.2,-2.8) M2(-2.4,-2.8) M3(-1.6,-2.8) M7(1.6,-2.8) M8(2.4,-2.8) M9(3.2,-2.8) N1(-3.2,-3.6) N2(-2.4,-3.6) N3(-1.6,-3.6) N7(1.6,-3.6) N8(2.4,-3.6) N9(3.2,-3.6) P1(-3.2,-4.4) P2(-2.4,-4.4) P3(-1.6,-4.4) P7(1.6,-4.4) P8(2.4,-4.4) P9(3.2,-4.4) R1(-3.2,-5.2) R2(-2.4,-5.2) R3(-1.6,-5.2) R7(1.6,-5.2) R8(2.4,-5.2) R9(3.2,-5.2) T1(-3.2,-6) T2(-2.4,-6) T3(-1.6,-6) T7(1.6,-6) T8(2.4,-6) T9(3.2,-6)
  silkscreen extent -3.93,-6.55 3.8,6.68, body extent -3.8,-6.55 3.8,6.55, height 1.21
ICC_P-WFBGA153_13X11P5_P050 [mm]
  round 0.23 smd mask+0.05: A1(-3.25,-3.25) A2(-3.25,-2.75) A3(-3.25,-2.25) A4(-3.25,-1.75) A5(-3.25,-1.25) A6(-3.25,-0.75) A7(-3.25,-0.25) A8(-3.25,0.25) A9(-3.25,0.75) A10(-3.25,1.25) A11(-3.25,1.75) A12(-3.25,2.25) A13(-3.25,2.75) A14(-3.25,3.25) B1(-2.75,-3.25) B2(-2.75,-2.75) B3(-2.75,-2.25) B4(-2.75,-1.75) B5(-2.75,-1.25) B6(-2.75,-0.75) B7(-2.75,-0.25) B8(-2.75,0.25) B9(-2.75,0.75) B10(-2.75,1.25) B11(-2.75,1.75) B12(-2.75,2.25) B13(-2.75,2.75) B14(-2.75,3.25) C1(-2.25,-3.25) C2(-2.25,-2.75) C3(-2.25,-2.25) C4(-2.25,-1.75) C5(-2.25,-1.25) C6(-2.25,-0.75) C7(-2.25,-0.25) C8(-2.25,0.25) C9(-2.25,0.75) C10(-2.25,1.25) C11(-2.25,1.75) C12(-2.25,2.25) C13(-2.25,2.75) C14(-2.25,3.25) D1(-1.75,-3.25) D2(-1.75,-2.75) D3(-1.75,-2.25) D4(-1.75,-1.75) D12(-1.75,2.25) D13(-1.75,2.75) D14(-1.75,3.25) E1(-1.25,-3.25) E2(-1.25,-2.75) E3(-1.25,-2.25) E5(-1.25,-1.25) E6(-1.25,-0.75) E7(-1.25,-0.25) E8(-1.25,0.25) E9(-1.25,0.75) E10(-1.25,1.25) E12(-1.25,2.25) E13(-1.25,2.75) E14(-1.25,3.25) F1(-0.75,-3.25) F2(-0.75,-2.75) F3(-0.75,-2.25) F5(-0.75,-1.25) F10(-0.75,1.25) F12(-0.75,2.25) F13(-0.75,2.75) F14(-0.75,3.25) G1(-0.25,-3.25) G2(-0.25,-2.75) G3(-0.25,-2.25) G5(-0.25,-1.25) G10(-0.25,1.25) G12(-0.25,2.25) G13(-0.25,2.75) G14(-0.25,3.25) H1(0.25,-3.25) H2(0.25,-2.75) H3(0.25,-2.25) H5(0.25,-1.25) H10(0.25,1.25) H12(0.25,2.25) H13(0.25,2.75) H14(0.25,3.25) J1(0.75,-3.25) J2(0.75,-2.75) J3(0.75,-2.25) J5(0.75,-1.25) J10(0.75,1.25) J12(0.75,2.25) J13(0.75,2.75) J14(0.75,3.25) K1(1.25,-3.25) K2(1.25,-2.75) K3(1.25,-2.25) K5(1.25,-1.25) K6(1.25,-0.75) K7(1.25,-0.25) K8(1.25,0.25) K9(1.25,0.75) K10(1.25,1.25) K12(1.25,2.25) K13(1.25,2.75) K14(1.25,3.25) L1(1.75,-3.25) L2(1.75,-2.75) L3(1.75,-2.25) L12(1.75,2.25) L13(1.75,2.75) L14(1.75,3.25) M1(2.25,-3.25) M2(2.25,-2.75) M3(2.25,-2.25) M4(2.25,-1.75) M5(2.25,-1.25) M6(2.25,-0.75) M7(2.25,-0.25) M8(2.25,0.25) M9(2.25,0.75) M10(2.25,1.25) M11(2.25,1.75) M12(2.25,2.25) M13(2.25,2.75) M14(2.25,3.25) N1(2.75,-3.25) N2(2.75,-2.75) N3(2.75,-2.25) N4(2.75,-1.75) N5(2.75,-1.25) N6(2.75,-0.75) N7(2.75,-0.25) N8(2.75,0.25) N9(2.75,0.75) N10(2.75,1.25) N11(2.75,1.75) N12(2.75,2.25) N13(2.75,2.75) N14(2.75,3.25) P1(3.25,-3.25) P2(3.25,-2.75) P3(3.25,-2.25) P4(3.25,-1.75) P5(3.25,-1.25) P6(3.25,-0.75) P7(3.25,-0.25) P8(3.25,0.25) P9(3.25,0.75) P10(3.25,1.25) P11(3.25,1.75) P12(3.25,2.25) P13(3.25,2.75) P14(3.25,3.25)
  silkscreen extent -6.78,-6.02 6.63,5.87, body extent -6.55,-5.8 6.55,5.8, height 1
ICC_QFN56-EPAD_6P5X6P5_P040 [mm] "MCD-03000"
  rect 0.55x0.21 smd mask+0.05: 1(-3.245,2.6) 14(-3.245,-2.6) 29(3.245,-2.6) 42(3.245,2.6)
  rect 0.7x0.21 smd mask+0.05: 2(-3.17,2.2) 3(-3.17,1.8) 4(-3.17,1.4) 5(-3.17,1) 6(-3.17,0.6) 7(-3.17,0.2) 8(-3.17,-0.2) 9(-3.17,-0.6) 10(-3.17,-1) 11(-3.17,-1.4) 12(-3.17,-1.8) 13(-3.17,-2.2) 30(3.17,-2.2) 31(3.17,-1.8) 32(3.17,-1.4) 33(3.17,-1) 34(3.17,-0.6) 35(3.17,-0.2) 36(3.17,0.2) 37(3.17,0.6) 38(3.17,1) 39(3.17,1.4) 40(3.17,1.8) 41(3.17,2.2)
  rect 0.21x0.55 smd mask+0.05: 15(-2.6,-3.245) 28(2.6,-3.245) 43(2.6,3.245) 56(-2.6,3.245)
  rect 0.21x0.7 smd mask+0.05: 16(-2.2,-3.17) 17(-1.8,-3.17) 18(-1.4,-3.17) 19(-1,-3.17) 20(-0.6,-3.17) 21(-0.2,-3.17) 22(0.2,-3.17) 23(0.6,-3.17) 24(1,-3.17) 25(1.4,-3.17) 26(1.8,-3.17) 27(2.2,-3.17) 44(2.2,3.17) 45(1.8,3.17) 46(1.4,3.17) 47(1,3.17) 48(0.6,3.17) 49(0.2,3.17) 50(-0.2,3.17) 51(-0.6,3.17) 52(-1,3.17) 53(-1.4,3.17) 54(-1.8,3.17) 55(-2.2,3.17)
  rect 4.7x4.7 smd mask+0.05: 57(0,0)
  Top Layer region: 2.97,2.495 2.82,2.495 2.82,2.555 2.97,2.705
  Top Layer region: 2.495,-2.97 2.495,-2.82 2.555,-2.82 2.705,-2.97
  Top Layer region: -2.97,2.495 -2.82,2.495 -2.82,2.555 -2.97,2.705
  Top Layer region: 2.97,-2.495 2.82,-2.495 2.82,-2.555 2.97,-2.705
  Top Layer region: -2.97,-2.495 -2.82,-2.495 -2.82,-2.555 -2.97,-2.705
  Top Layer region: 2.495,2.97 2.495,2.82 2.555,2.82 2.705,2.97
  Top Layer region: -2.495,-2.97 -2.495,-2.82 -2.555,-2.82 -2.705,-2.97
  Top Layer region: -2.495,2.97 -2.495,2.82 -2.555,2.82 -2.705,2.97
  silkscreen extent -3.44,3 -3.01,3.42, body extent -3.25,-3.25 3.25,3.25, height 0.91
ICC_TFBGA361_16X16_P080 [mm] "MCD-04441"
  round 0.3 smd mask+0.05: A1(-7.2,7.2) A2(-6.4,7.2) A3(-5.6,7.2) A4(-4.8,7.2) A5(-4,7.2) A6(-3.2,7.2) A7(-2.4,7.2) A8(-1.6,7.2) A9(-0.8,7.2) A10(0,7.2) A11(0.8,7.2) A12(1.6,7.2) A13(2.4,7.2) A14(3.2,7.2) A15(4,7.2) A16(4.8,7.2) A17(5.6,7.2) A18(6.4,7.2) A19(7.2,7.2) B1(-7.2,6.4) B2(-6.4,6.4) B3(-5.6,6.4) B4(-4.8,6.4) B5(-4,6.4) B6(-3.2,6.4) B7(-2.4,6.4) B8(-1.6,6.4) B9(-0.8,6.4) B10(0,6.4) B11(0.8,6.4) B12(1.6,6.4) B13(2.4,6.4) B14(3.2,6.4) B15(4,6.4) B16(4.8,6.4) B17(5.6,6.4) B18(6.4,6.4) B19(7.2,6.4) C1(-7.2,5.6) C2(-6.4,5.6) C3(-5.6,5.6) C4(-4.8,5.6) C5(-4,5.6) C6(-3.2,5.6) C7(-2.4,5.6) C8(-1.6,5.6) C9(-0.8,5.6) C10(0,5.6) C11(0.8,5.6) C12(1.6,5.6) C13(2.4,5.6) C14(3.2,5.6) C15(4,5.6) C16(4.8,5.6) C17(5.6,5.6) C18(6.4,5.6) C19(7.2,5.6) D1(-7.2,4.8) D2(-6.4,4.8) D3(-5.6,4.8) D4(-4.8,4.8) D5(-4,4.8) D6(-3.2,4.8) D7(-2.4,4.8) D8(-1.6,4.8) D9(-0.8,4.8) D10(0,4.8) D11(0.8,4.8) D12(1.6,4.8) D13(2.4,4.8) D14(3.2,4.8) D15(4,4.8) D16(4.8,4.8) D17(5.6,4.8) D18(6.4,4.8) D19(7.2,4.8) E1(-7.2,4) E2(-6.4,4) E3(-5.6,4) E4(-4.8,4) E5(-4,4) E6(-3.2,4) E7(-2.4,4) E8(-1.6,4) E9(-0.8,4) E10(0,4) E11(0.8,4) E12(1.6,4) E13(2.4,4) E14(3.2,4) E15(4,4) E16(4.8,4) E17(5.6,4) E18(6.4,4) E19(7.2,4) F1(-7.2,3.2) F2(-6.4,3.2) F3(-5.6,3.2) F4(-4.8,3.2) F5(-4,3.2) F6(-3.2,3.2) F7(-2.4,3.2) F8(-1.6,3.2) F9(-0.8,3.2) F10(0,3.2) F11(0.8,3.2) F12(1.6,3.2) F13(2.4,3.2) F14(3.2,3.2) F15(4,3.2) F16(4.8,3.2) F17(5.6,3.2) F18(6.4,3.2) F19(7.2,3.2) G1(-7.2,2.4) G2(-6.4,2.4) G3(-5.6,2.4) G4(-4.8,2.4) G5(-4,2.4) G6(-3.2,2.4) G7(-2.4,2.4) G8(-1.6,2.4) G9(-0.8,2.4) G10(0,2.4) G11(0.8,2.4) G12(1.6,2.4) G13(2.4,2.4) G14(3.2,2.4) G15(4,2.4) G16(4.8,2.4) G17(5.6,2.4) G18(6.4,2.4) G19(7.2,2.4) H1(-7.2,1.6) H2(-6.4,1.6) H3(-5.6,1.6) H4(-4.8,1.6) H5(-4,1.6) H6(-3.2,1.6) H7(-2.4,1.6) H8(-1.6,1.6) H9(-0.8,1.6) H10(0,1.6) H11(0.8,1.6) H12(1.6,1.6) H13(2.4,1.6) H14(3.2,1.6) H15(4,1.6) H16(4.8,1.6) H17(5.6,1.6) H18(6.4,1.6) H19(7.2,1.6) J1(-7.2,0.8) J2(-6.4,0.8) J3(-5.6,0.8) J4(-4.8,0.8) J5(-4,0.8) J6(-3.2,0.8) J7(-2.4,0.8) J8(-1.6,0.8) J9(-0.8,0.8) J10(0,0.8) J11(0.8,0.8) J12(1.6,0.8) J13(2.4,0.8) J14(3.2,0.8) J15(4,0.8) J16(4.8,0.8) J17(5.6,0.8) J18(6.4,0.8) J19(7.2,0.8) K1(-7.2,0) K2(-6.4,0) K3(-5.6,0) K4(-4.8,0) K5(-4,0) K6(-3.2,0) K7(-2.4,0) K8(-1.6,0) K9(-0.8,0) K10(0,0) K11(0.8,0) K12(1.6,0) K13(2.4,0) K14(3.2,0) K15(4,0) K16(4.8,0) K17(5.6,0) K18(6.4,0) K19(7.2,0) L1(-7.2,-0.8) L2(-6.4,-0.8) L3(-5.6,-0.8) L4(-4.8,-0.8) L5(-4,-0.8) L6(-3.2,-0.8) L7(-2.4,-0.8) L8(-1.6,-0.8) L9(-0.8,-0.8) L10(0,-0.8) L11(0.8,-0.8) L12(1.6,-0.8) L13(2.4,-0.8) L14(3.2,-0.8) L15(4,-0.8) L16(4.8,-0.8) L17(5.6,-0.8) L18(6.4,-0.8) L19(7.2,-0.8) M1(-7.2,-1.6) M2(-6.4,-1.6) M3(-5.6,-1.6) M4(-4.8,-1.6) M5(-4,-1.6) M6(-3.2,-1.6) M7(-2.4,-1.6) M8(-1.6,-1.6) M9(-0.8,-1.6) M10(0,-1.6) M11(0.8,-1.6) M12(1.6,-1.6) M13(2.4,-1.6) M14(3.2,-1.6) M15(4,-1.6) M16(4.8,-1.6) M17(5.6,-1.6) M18(6.4,-1.6) M19(7.2,-1.6) N1(-7.2,-2.4) N2(-6.4,-2.4) N3(-5.6,-2.4) N4(-4.8,-2.4) N5(-4,-2.4) N6(-3.2,-2.4) N7(-2.4,-2.4) N8(-1.6,-2.4) N9(-0.8,-2.4) N10(0,-2.4) N11(0.8,-2.4) N12(1.6,-2.4) N13(2.4,-2.4) N14(3.2,-2.4) N15(4,-2.4) N16(4.8,-2.4) N17(5.6,-2.4) N18(6.4,-2.4) N19(7.2,-2.4) P1(-7.2,-3.2) P2(-6.4,-3.2) P3(-5.6,-3.2) P4(-4.8,-3.2) P5(-4,-3.2) P6(-3.2,-3.2) P7(-2.4,-3.2) P8(-1.6,-3.2) P9(-0.8,-3.2) P10(0,-3.2) P11(0.8,-3.2) P12(1.6,-3.2) P13(2.4,-3.2) P14(3.2,-3.2) P15(4,-3.2) P16(4.8,-3.2) P17(5.6,-3.2) P18(6.4,-3.2) P19(7.2,-3.2) R1(-7.2,-4) R2(-6.4,-4) R3(-5.6,-4) R4(-4.8,-4) R5(-4,-4) R6(-3.2,-4) R7(-2.4,-4) R8(-1.6,-4) R9(-0.8,-4) R10(0,-4) R11(0.8,-4) R12(1.6,-4) R13(2.4,-4) R14(3.2,-4) R15(4,-4) R16(4.8,-4) R17(5.6,-4) R18(6.4,-4) R19(7.2,-4) T1(-7.2,-4.8) T2(-6.4,-4.8) T3(-5.6,-4.8) T4(-4.8,-4.8) T5(-4,-4.8) T6(-3.2,-4.8) T7(-2.4,-4.8) T8(-1.6,-4.8) T9(-0.8,-4.8) T10(0,-4.8) T11(0.8,-4.8) T12(1.6,-4.8) T13(2.4,-4.8) T14(3.2,-4.8) T15(4,-4.8) T16(4.8,-4.8) T17(5.6,-4.8) T18(6.4,-4.8) T19(7.2,-4.8) U1(-7.2,-5.6) U2(-6.4,-5.6) U3(-5.6,-5.6) U4(-4.8,-5.6) U5(-4,-5.6) U6(-3.2,-5.6) U7(-2.4,-5.6) U8(-1.6,-5.6) U9(-0.8,-5.6) U10(0,-5.6) U11(0.8,-5.6) U12(1.6,-5.6) U13(2.4,-5.6) U14(3.2,-5.6) U15(4,-5.6) U16(4.8,-5.6) U17(5.6,-5.6) U18(6.4,-5.6) U19(7.2,-5.6) V1(-7.2,-6.4) V2(-6.4,-6.4) V3(-5.6,-6.4) V4(-4.8,-6.4) V5(-4,-6.4) V6(-3.2,-6.4) V7(-2.4,-6.4) V8(-1.6,-6.4) V9(-0.8,-6.4) V10(0,-6.4) V11(0.8,-6.4) V12(1.6,-6.4) V13(2.4,-6.4) V14(3.2,-6.4) V15(4,-6.4) V16(4.8,-6.4) V17(5.6,-6.4) V18(6.4,-6.4) V19(7.2,-6.4) W1(-7.2,-7.2) W2(-6.4,-7.2) W3(-5.6,-7.2) W4(-4.8,-7.2) W5(-4,-7.2) W6(-3.2,-7.2) W7(-2.4,-7.2) W8(-1.6,-7.2) W9(-0.8,-7.2) W10(0,-7.2) W11(0.8,-7.2) W12(1.6,-7.2) W13(2.4,-7.2) W14(3.2,-7.2) W15(4,-7.2) W16(4.8,-7.2) W17(5.6,-7.2) W18(6.4,-7.2) W19(7.2,-7.2)
  silkscreen extent -8,-8 8,8, body extent -8,-8 8,8, height 1.2
IND_2016_MURATA_LQM2MPN2R2NG0 [mm]
  rect 0.8x1.8 smd mask+0.05: 1(-0.8,0) 2(0.8,0)
  silkscreen extent -0.28,-0.87 0.28,0.87, body extent -1.07,-0.87 1.08,0.87, height 1
IND_2520_TOKO_DFE252012P [mm]
  rect 0.8x2 smd mask+0.05: 1(-1,0) 2(1,0)
  silkscreen extent -1.35,-1.12 1.35,1.12, body extent -1.35,-1.1 1.35,1.1, height 2
LED_0603_OSRAM_LG-Q396-PS-35_GREEN_1A2K_H0P4 [mm]
  rect 0.8x0.8 smd mask+0.05: 1(-0.75,0) 2(0.75,0)
  silkscreen extent -0.85,-0.53 1.28,0.53, body extent -0.85,-0.45 0.85,0.45, height 0.6
LINK200 [mm]
  rect 0.2x0.35 smd paste-10 mask+0.05: 1(0,-0.225) 2(0,0.225)
R0201_H0P23 [mm] "MCD-00702"
  rect 0.4x0.5 smd mask+0.05: 1(-0.3,0) 2(0.3,0)
  body extent -0.32,-0.17 0.32,0.17, height 0.26
R0402 [mm]
  rect 0.51x0.7 smd mask+0.05: 1(-0.45,0) 2(0.45,0)
  body extent -0.52,-0.3 0.52,0.3, height 0.4
SWI_WE_434121025816 [mm] "MCD-03492"
  rect 1.5x1.4 smd: 1(-3.25,0) 2(3.25,0)
  silkscreen extent -3,-1.95 3,1.95, body extent -3.65,-1.95 3.65,1.95, height 2.51
TP_SMD_1MM [mm]
  round 1 smd paste-10 mask+0.05: 1(0,0)
  silkscreen extent -0.7,-0.7 0.7,0.7

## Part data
B2: library part MCD-03492, "Switch tactile, SPST-NO, 50mA, 12V, 6x3.8mm", Manufacturer="WURTH ELEKTRONIC", Manufacturer_Part_Number=434121025816, Package=6x3.8mm
C18 C42: library part MCD-01796, "Capacitor, Tantalum, 100uF, 6V3, 40mR, +/-20%,  Type_B (3528 metric), T=1.9mm", Manufacturer=AVX, Manufacturer_Part_Number=TCJB107M006R0040, Package="3528 (metric)"
C19 C21 C152 C157 C186 C187 C193 C204 C206 C207: library part MCD-03139, "Capacitor, MLCC, 22uF, 10V, X5R, +/-20%, 0805, T=1,25mm", Manufacturer=MURATA, Manufacturer_Part_Number=GRM21BR61A226ME51L, Package=0805
C20 C29 C30 C32 C38 C184 C199: library part MCD-00099, "Capacitor, MLCC, 10uF, 10V, X5R, +/-10%, 0603, T=0,8mm", Alternate_Manufacturer=N/A, Manufacturer=MURATA, Manufacturer_Part_Number=GRM188R61A106KE69D, Package=0603
C22 C23 C24 C26 C27 C28 C34 C35 C36 C37 C41 C183 C200 C202: library part MCD-00100, "Capacitor, MLCC, 22uF, 6V3, X5R, +/-20%, 0603, T=0,8mm", Alternate_Manufacturer=N/A, Manufacturer=MURATA, Manufacturer_Part_Number=GRM188R60J226MEA0J, Package=0603
C33: library part MCD-00011, "Capacitor, MLCC, 10nF, 16V, X7R, 10%, 0402, T=0.5mm", Manufacturer=YAGEO, Manufacturer_Part_Number=CC0402KRX7R7BB103, Package=C0402
C39 C40 C145 C254: library part MCD-03140, "Capacitor, MLCC, 10uF, 6.3V, X5R, +/-20%, 0402, T=0.5mm", Manufacturer=MURATA, Manufacturer_Part_Number=GRM155R60J106ME05D, Package=0402
C43 C153 C154 C188: library part MCD-00095, "Capacitor, MLCC, 1uF, 25V, X5R, +/-10%, 0402, T=0.5mm", Manufacturer=MURATA, Manufacturer_Part_Number=GRM155R61E105KA12, Package=0402
C67 C159 C163 C164 C166 C167 C168 C169 C173 C174 C175 C176 C191 C192 C195 C201 C360 C372 C377 C378 C380 C381 C382 C383 C386 C387 C388 C389 C390 C399 C400 C402: library part MCD-02377, "Capacitor, MLCC, 1uF, 6.3V, X5R, +/-20%, 0201, T=0,3mm", Alternate_Manufacturer=N/A, Manufacturer=MURATA, Manufacturer_Part_Number=GRM033R60J105MEA2, Package=0201
C70 C82 C94 C104 C105 C106 C144 C146 C160 C177 C178 C179 C181 C182 C218 C226 C239 C252 C255 C256 C257 C258 C259 C261 C265 C266 C479: library part MCD-00006, "Capacitor, MLCC, 100nF, 16V, X7R, +/-10%, 0402, T=0.5mm", Alternate_Manufacturer=MURATA, Alternate_Manufacturer_Part_Number=GCM155R71C104KA55D, Manufacturer=YAGEO, Manufacturer_Part_Number=CC0402KRX7R7BB104, Package=0402
C79: library part MCD-02235, "Capacitor, MLCC, 2.2uF, 10V, X5R,+/-10%, 0201, T=0.5mm", Manufacturer=MURATA, Manufacturer_Part_Number=GRM033R61A225KE47D, Package=0201
C81 C86 C90 C92: library part MCD-00674, "Capacitor, MLCC, 6.8pF, 50V, NPO, +-0.25pF, 0402, T=0.5mm", Alternate_Manufacturer=N/A, Manufacturer=YAGEO, Manufacturer_Part_Number=CC0402CRNPO9BN6R8, Package=0402
C87: library part MCD-00006, "Capacitor,100nF,16V,X7R,10%,0402", Alternate_Manufacturer=MURATA, Alternate_Manufacturer_Part_Number=GCM155R71C104KA55D, Manufacturer=YAGEO, Manufacturer_Part_Number=CC0402KRX7R7BB104, Package=0402
C88: library part MCD-01823, "Capacitor, MLCC, 2.2uF, 6V3, X5R,+/-10%, 0402, T=0.5mm", Alternate_Manufacturer=N/A, Manufacturer=MURATA, Manufacturer_Part_Number=GRM155R60J225KE95D, Package=0402
C91 C141 C142 C156 C189 C190 C208 C209 C217: library part MCD-01356, "Capacitor, MLCC, 4.7uF, 6V3, X5R, +/-20%, 0402, T=0.5mm", Manufacturer=MURATA, Manufacturer_Part_Number=GRM155R60J475ME47, Package=0402
C112 C172: library part MCD-01341, "Capacitor, MLCC, 10uF, 6V3, X5R, +/-20%, 0603, T=0,8mm", Alternate_Manufacturer=MURATA, Alternate_Manufacturer_Part_Number=GRM188R60J106ME84D, Manufacturer_Part_Number=GRM188R60J106ME47D, Package=0603
C143 C161 C165 C171 C196 C210 C342 C344 C352 C353 C354 C355 C356 C357 C393 C404 C406 C407 C408 C409 C417: library part MCD-01535, "Capacitor, MLCC,100nF, 10V, X7R, +/-10%, 0201, T=0.3mm", Alternate_Manufacturer=N/A, Manufacturer=MURATA, Manufacturer_Part_Number=GRM033R61A104KE15, Package=0201
C155: library part MCD-02198, "Capacitor, MLCC, 10nF, 50V, X7R, +/-10%, 0402, T=0.5mm", Manufacturer=YAGEO, Manufacturer_Part_Number=CC0402KRX7R9BB103, Package=0402
C180 C478 C481: library part MCD-02606, "Capacitor, MLCC, 2.2uF, 6.3V, X5R, +/-10%, 0402, T=0.5mm", Manufacturer=YAGEO, Manufacturer_Part_Number=CC0402KRX5R5BB225, Package=0402
C384: library part MCD-01534, "Capacitor, MLCC, 4,7uF, 6V3, X5R, +/-20%, 0201, T=0.5mm", Alternate_Manufacturer=N/A, Manufacturer=MURATA, Manufacturer_Part_Number=GRM035R60J475ME15, Package=0201
CN12: library part MCD-00655, "Header 2 circuits, 1.25mm Pitch ,  Vertical, with Friction Lock", Alternate_Manufacturer=N/A, Manufacturer=MOLEX, Manufacturer_Part_Number=53047-0210
D5: library part MCD-00034, Manufacturer=STMICROELECTRONICS, Manufacturer_HQ_COO=EU, Package=SOD323
D6: library part MCD-03280, "Diode, Schottky, Dual Common Cathode, 0V3, 300mA, 40V, SOT-23", Manufacturer=STMICROELECTRONICS, Manufacturer_Part_Number=BAT54CFILM, Package=SOT23
L1 L6: library part MCD-03143, "Inductor, 2.2uH, +/-20%, Itemp= 1700mA, Isat= 2400mA, 0R140, 0806, T=1mm", Manufacturer=MURATA, Manufacturer_Part_Number=DFE201610E-2R2M{}P2, Package=0806
L2 L4: library part MCD-03142, "Inductor, 0.68uH, +/-20%, Itemp= 3900mA, Isat= 5400mA, 0R031, 1008, T=1.2mm", Manufacturer=MURATA, Manufacturer_Part_Number=DFE252012F-R68M{}P2, Package=1008
L3 L5 L7: library part MCD-03141, "Inductor, 0.68uH, +/-20%, Itemp= 3100mA, Isat= 4300mA, 0R043, 0806, T=1mm", Manufacturer=MURATA, Manufacturer_Part_Number=DFE201610E-R68M{}P2, Package=0806
LD11: library part MCD-00588, "LED Green, 0603 SMD, Forward Voltage Typ=2V, Max=2.5V", Alternate_Manufacturer="VISHAY SEMICONDUCTOR OPTO DIVISION", Alternate_Manufacturer_Part_Number=VLMTG1300-GS08, Manufacturer="OSRAM OPTO SEMICONDUCTORS", Manufacturer_Part_Number="LG Q396-PS-35", Package="LED 0603"
LNK1 LNK2 LNK4 LNK7 LNK8 LNK11: library part MCD-02777, "Track link on PCB 200um width for layout routing", Manufacturer=N/A
R2 R3 R46 R57 R59 R60 R64 R81 R197 R199: library part MCD-00052, "Resistor,0R,0402,5%,1/16W", Alternate_Manufacturer=N/A, Manufacturer=YAGEO, Manufacturer_Part_Number=RC0402JR-070RL, Package=0402
R27 R176 R272: library part MCD-00053, "Resistor,10K,0402,1%,1/16W", Alternate_Manufacturer=N/A, Manufacturer=YAGEO, Manufacturer_Part_Number=RC0402FR-0710KL, Package=0402
R37 R44 R49 R248: library part MCD-00053, "Resistor,10K,0402,1%,1/16W", Manufacturer=YAGEO, Manufacturer_Part_Number=RC0402FR-0710KL, Package=0402
R66: library part MCD-00058, "Resistor, 20R, 0402, +/-1%, 1/16W", Alternate_Manufacturer=N/A, Manufacturer=YAGEO, Manufacturer_Part_Number=RC0402FR-0720RL, Package=0402
R67: library part MCD-00052, "Resistor, 0R, 0402, +/-5%, 1/16W", Manufacturer=YAGEO, Manufacturer_Part_Number=RC0402JR-070RL, Package=0402
R112 R113 R179: library part MCD-02253, "Resistor,240R,0201,1%,1/20W", Alternate_Manufacturer=N/A, Manufacturer=YAGEO, Manufacturer_Part_Number=RC0201FR-07240RL, Package=R0201
R116 R118: library part MCD-00061, "Resistor, 1K, 0402, +/-1%,1/16W", Manufacturer=YAGEO, Manufacturer_Part_Number=RC0402FR-071KL, Package=0402
R161 R162 R196: library part MCD-00417, "Resistor,200R,0402,1%,1/16W", Alternate_Manufacturer=N/A, Manufacturer=YAGEO, Manufacturer_Part_Number=RC0402FR-07200RL, Package=0402
R177: library part MCD-01819, "Resistor,100R,0402,0,5%,1/16W,±100ppm/°C", Alternate_Manufacturer=N/A, Manufacturer=YAGEO, Manufacturer_Part_Number=RC0402DR-07100RL, Package=0402
R210: library part MCD-00441, "Resistor,270R,0402,1%,1/16W", Manufacturer=YAGEO, Manufacturer_Part_Number=RC0402FR-07270RL, Package=0402
R252 R253 R254 R255 R256 R257 R258 R259 R263 R264 R265 R266 R268 R271 R273 R275 R276 R277 R278 R279 R280 R281 R282 R283 R284: library part MCD-00054, "Resistor, 56R, 0402, +/-1%, 1/16W", Alternate_Manufacturer=N/A, Manufacturer=YAGEO, Manufacturer_Part_Number=RC0402FR-0756RL, Package=0402
R260 R261: library part MCD-00068, "Resistor,1K5,0402,1%,1/16W", Manufacturer=YAGEO, Manufacturer_Part_Number=RC0402FR-071K5L, Package=0402
TP9: library part MCD-00074, "Test Point 1mm", Manufacturer=n/a, Manufacturer_HQ_COO=Unknown
U10: library part MCD-04441, "MPU, Dual Core ARM cortex-A35 64-bit + M33 32-bit,  808KB SRAM, With Crypto", Manufacturer=STMICROELECTRONICS, Manufacturer_Part_Number=STM32MP257FAJ3, Package=TFBGA361
U17: library part MCD-04020, "Memory, DDR4 SDRAM, 1V2, 32Gbit, 1.6GHz, FBGA96", Manufacturer=MICRON, Package=FBGA96
U24: library part MCD-02799, "Memory, eMMC, 4GB, 15nm ,WFBGA , 153 pins", Manufacturer=KIOXIA, Manufacturer_Part_Number=THGBMTG5D1LBAIL, Package=WFBGA153
U26: library part MCD-03000, "STPMIC2", Manufacturer=STMICROELECTRONICS, Package=VQFN
X1: library part MCD-01479, "Crystal, 32.768kHz, 6pF, +/-20ppm, 80K, 2.05x1.2mm", Manufacturer=NDK, Manufacturer_Part_Number=NX2012SA-32.768KHZ-EXS00A-MU00527, Package=2.05x1.2mm
X2: library part MCD-02344, "Crystal, 40MHz, 6pF, +/-20ppm, 80R, 1.6x1.2mm", Manufacturer=NDK, Manufacturer_Part_Number=NX1612SA-40MHZ-EXS00A-CS13836, Package=1.6x1.2mm

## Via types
v1: diameter 0.55, hole 0.35, Top Layer to Bottom Layer, 344 vias
v2: diameter 0.5, hole 0.2, Top Layer to Bottom Layer, 250 vias
v3: diameter 0.4, hole 0.2, Top Layer to Bottom Layer, tented both sides, 180 vias
v4: diameter 0.4, hole 0.2, Top Layer to Bottom Layer, 76 vias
